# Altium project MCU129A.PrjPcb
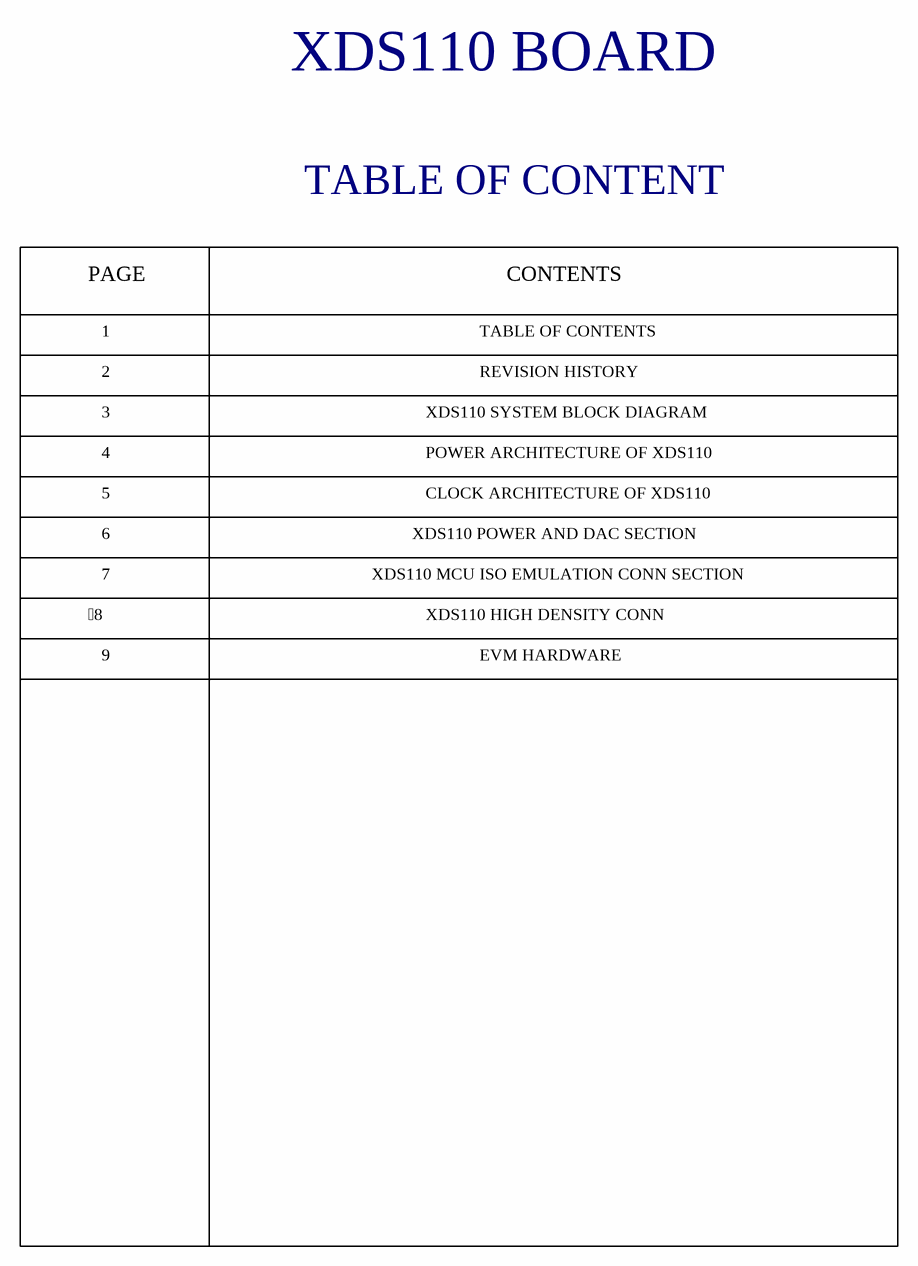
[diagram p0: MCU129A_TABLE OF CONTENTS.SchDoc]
DrawnBy: Texas Instruments; EVM_orderable: XDS110ISO-EVM; PCB_REV: A; PRJ_Customer: Public Release; PRJ_Engineer: Gus Martinez; PRJ_Number: MCU129; PRJ_Title: C2000 XDS110 Plug -In Board; SCH_REV: A; TID: N/A
9 sheets, 170 parts. Net scope: global (net labels, ports and power ports of the same name join across sheets).
Board file: MCU129A.PcbDoc
Sheets:
  MCU129A_TABLE OF CONTENTS.SchDoc
  MCU129A_REVISION_HISTORY.SchDoc
  MCU129A_SYSTEM_BLOCK_DIAG.SchDoc
  MCU129A_POWER_ARCHITECT.SchDoc
  MCU129A_CLOCK_ARCHITECTURE.SchDoc
  MCU129A_POWER_DAC_SECTION.SchDoc
  MCU129A_MCU_ISO_EMULATION_CONN.SchDoc
  MCU129A_HIGH_DENSITY_CONN.SchDoc
  MCU129A_EVM_Hardware.SchDoc

## Sheet MCU129A_TABLE OF CONTENTS.SchDoc
size 431 x 279 mm; Date: Not shown in title block; ApprovedBy: Not shown in title block; CheckedBy: Not shown in title block; Author: Not shown in title block; CompanyName: Not shown in title block; Engineer: Not shown in title block; Organization: Not shown in title block; Address1: Not shown in title block; Address2: Not shown in title block; Address3: Not shown in title block; Address4: Not shown in title block; DocumentNumber: 1; Revision: Use project parameter SCH_Rev; SheetNumber: 1; SheetTotal: 9; PageSetup: Record=PageOptions¦CenterHorizontal=True¦CenterVertical=True¦PrintScale=1.00¦XCorrection=1.00¦YCorrection=1.00¦PrintKind=0¦BorderSize=5000000¦LeftOffset=0¦BottomOffset=0¦Orientation=2¦PaperLength=1000¦PaperWidth=1000¦Scale=100¦PaperSource=15¦PrintQuality=600¦MediaType=1¦DitherType=10¦PaperKind=Letter¦PrintScaleMode=1

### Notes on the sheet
- XDS110 BOARD
- TABLE OF CONTENT
- PAGE
- 1
- TABLE OF CONTENTS
- CONTENTS
- 2
- REVISION HISTORY
- 3
- 4
- XDS110 SYSTEM BLOCK DIAGRAM
- POWER ARCHITECTURE OF XDS110
- 5
- 6
- XDS110 POWER AND DAC SECTION
- CLOCK ARCHITECTURE OF XDS110
- 7
- XDS110 MCU ISO EMULATION CONN SECTION
- 8
- 9
- XDS110 HIGH DENSITY CONN
- EVM HARDWARE

## Sheet MCU129A_REVISION_HISTORY.SchDoc
size 431 x 279 mm; Date: Not shown in title block; ApprovedBy: Not shown in title block; CheckedBy: Not shown in title block; Author: Not shown in title block; CompanyName: Not shown in title block; Engineer: Not shown in title block; Organization: Not shown in title block; Address1: Not shown in title block; Address2: Not shown in title block; Address3: Not shown in title block; Address4: Not shown in title block; DocumentNumber: 2; Revision: Use project parameter SCH_Rev; SheetNumber: 2; SheetTotal: 9; PageSetup: Record=PageOptions¦CenterHorizontal=True¦CenterVertical=True¦PrintScale=1.00¦XCorrection=1.00¦YCorrection=1.00¦PrintKind=0¦BorderSize=5000000¦LeftOffset=0¦BottomOffset=0¦Orientation=2¦PaperLength=1000¦PaperWidth=1000¦Scale=100¦PaperSource=15¦PrintQuality=600¦MediaType=1¦DitherType=10¦PaperKind=Letter¦PrintScaleMode=1
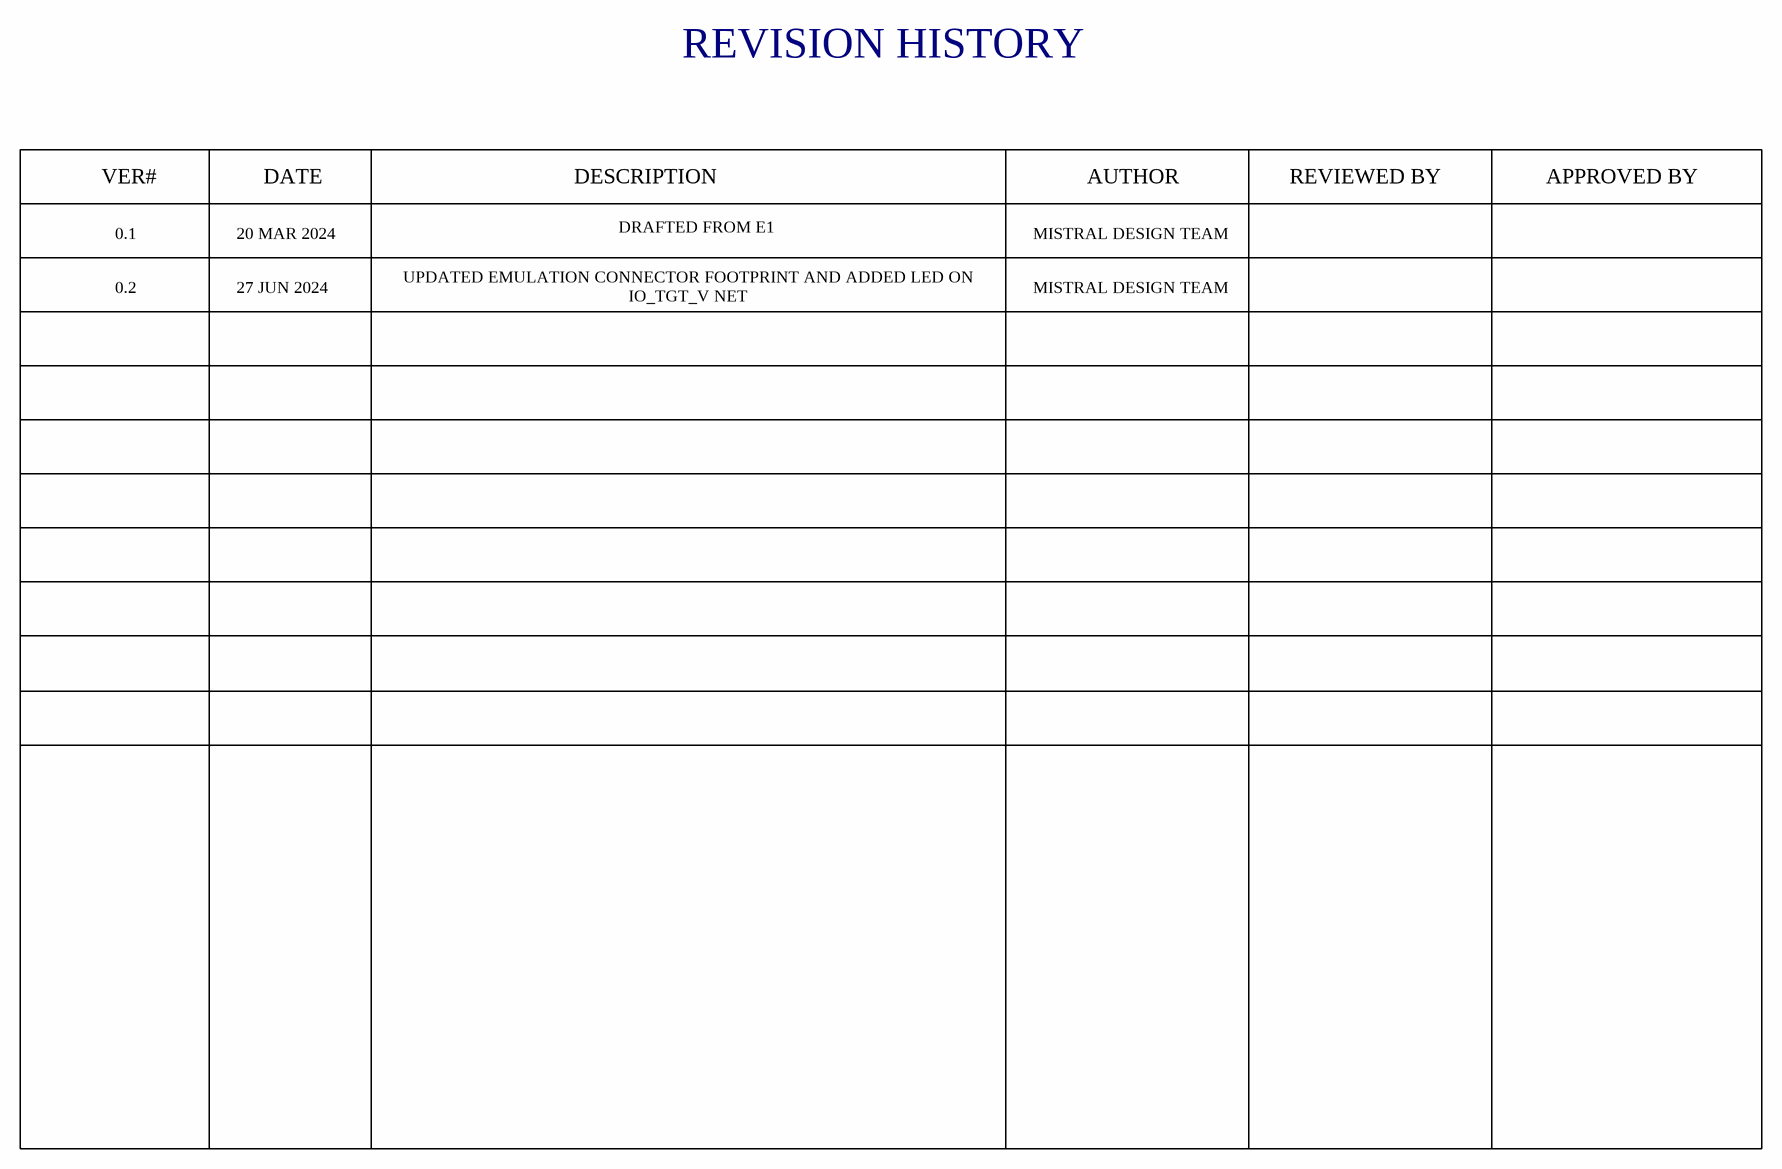
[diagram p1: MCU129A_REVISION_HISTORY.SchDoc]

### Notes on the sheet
- REVISION HISTORY
- VER#
- 0.1
- 20 MAR 2024
- DATE
- DESCRIPTION
- DRAFTED FROM E1
- MISTRAL DESIGN TEAM
- AUTHOR
- REVIEWED BY
- APPROVED BY
- 0.2
- 27 JUN 2024
- UPDATED EMULATION CONNECTOR FOOTPRINT AND ADDED LED ON IO_TGT_V NET

## Sheet MCU129A_SYSTEM_BLOCK_DIAG.SchDoc
size 431 x 279 mm; Date: Not shown in title block; ApprovedBy: Not shown in title block; CheckedBy: Not shown in title block; Author: Not shown in title block; CompanyName: Not shown in title block; Engineer: Not shown in title block; Organization: Not shown in title block; Address1: Not shown in title block; Address2: Not shown in title block; Address3: Not shown in title block; Address4: Not shown in title block; DocumentNumber: 3; Revision: Use project parameter SCH_Rev; SheetNumber: 3; SheetTotal: 9; PageSetup: Record=PageOptions¦CenterHorizontal=True¦CenterVertical=True¦PrintScale=1.00¦XCorrection=1.00¦YCorrection=1.00¦PrintKind=0¦BorderSize=5000000¦LeftOffset=0¦BottomOffset=0¦Orientation=2¦PaperLength=1000¦PaperWidth=1000¦Scale=100¦PaperSource=15¦PrintQuality=600¦MediaType=1¦DitherType=10¦PaperKind=Letter¦PrintScaleMode=1
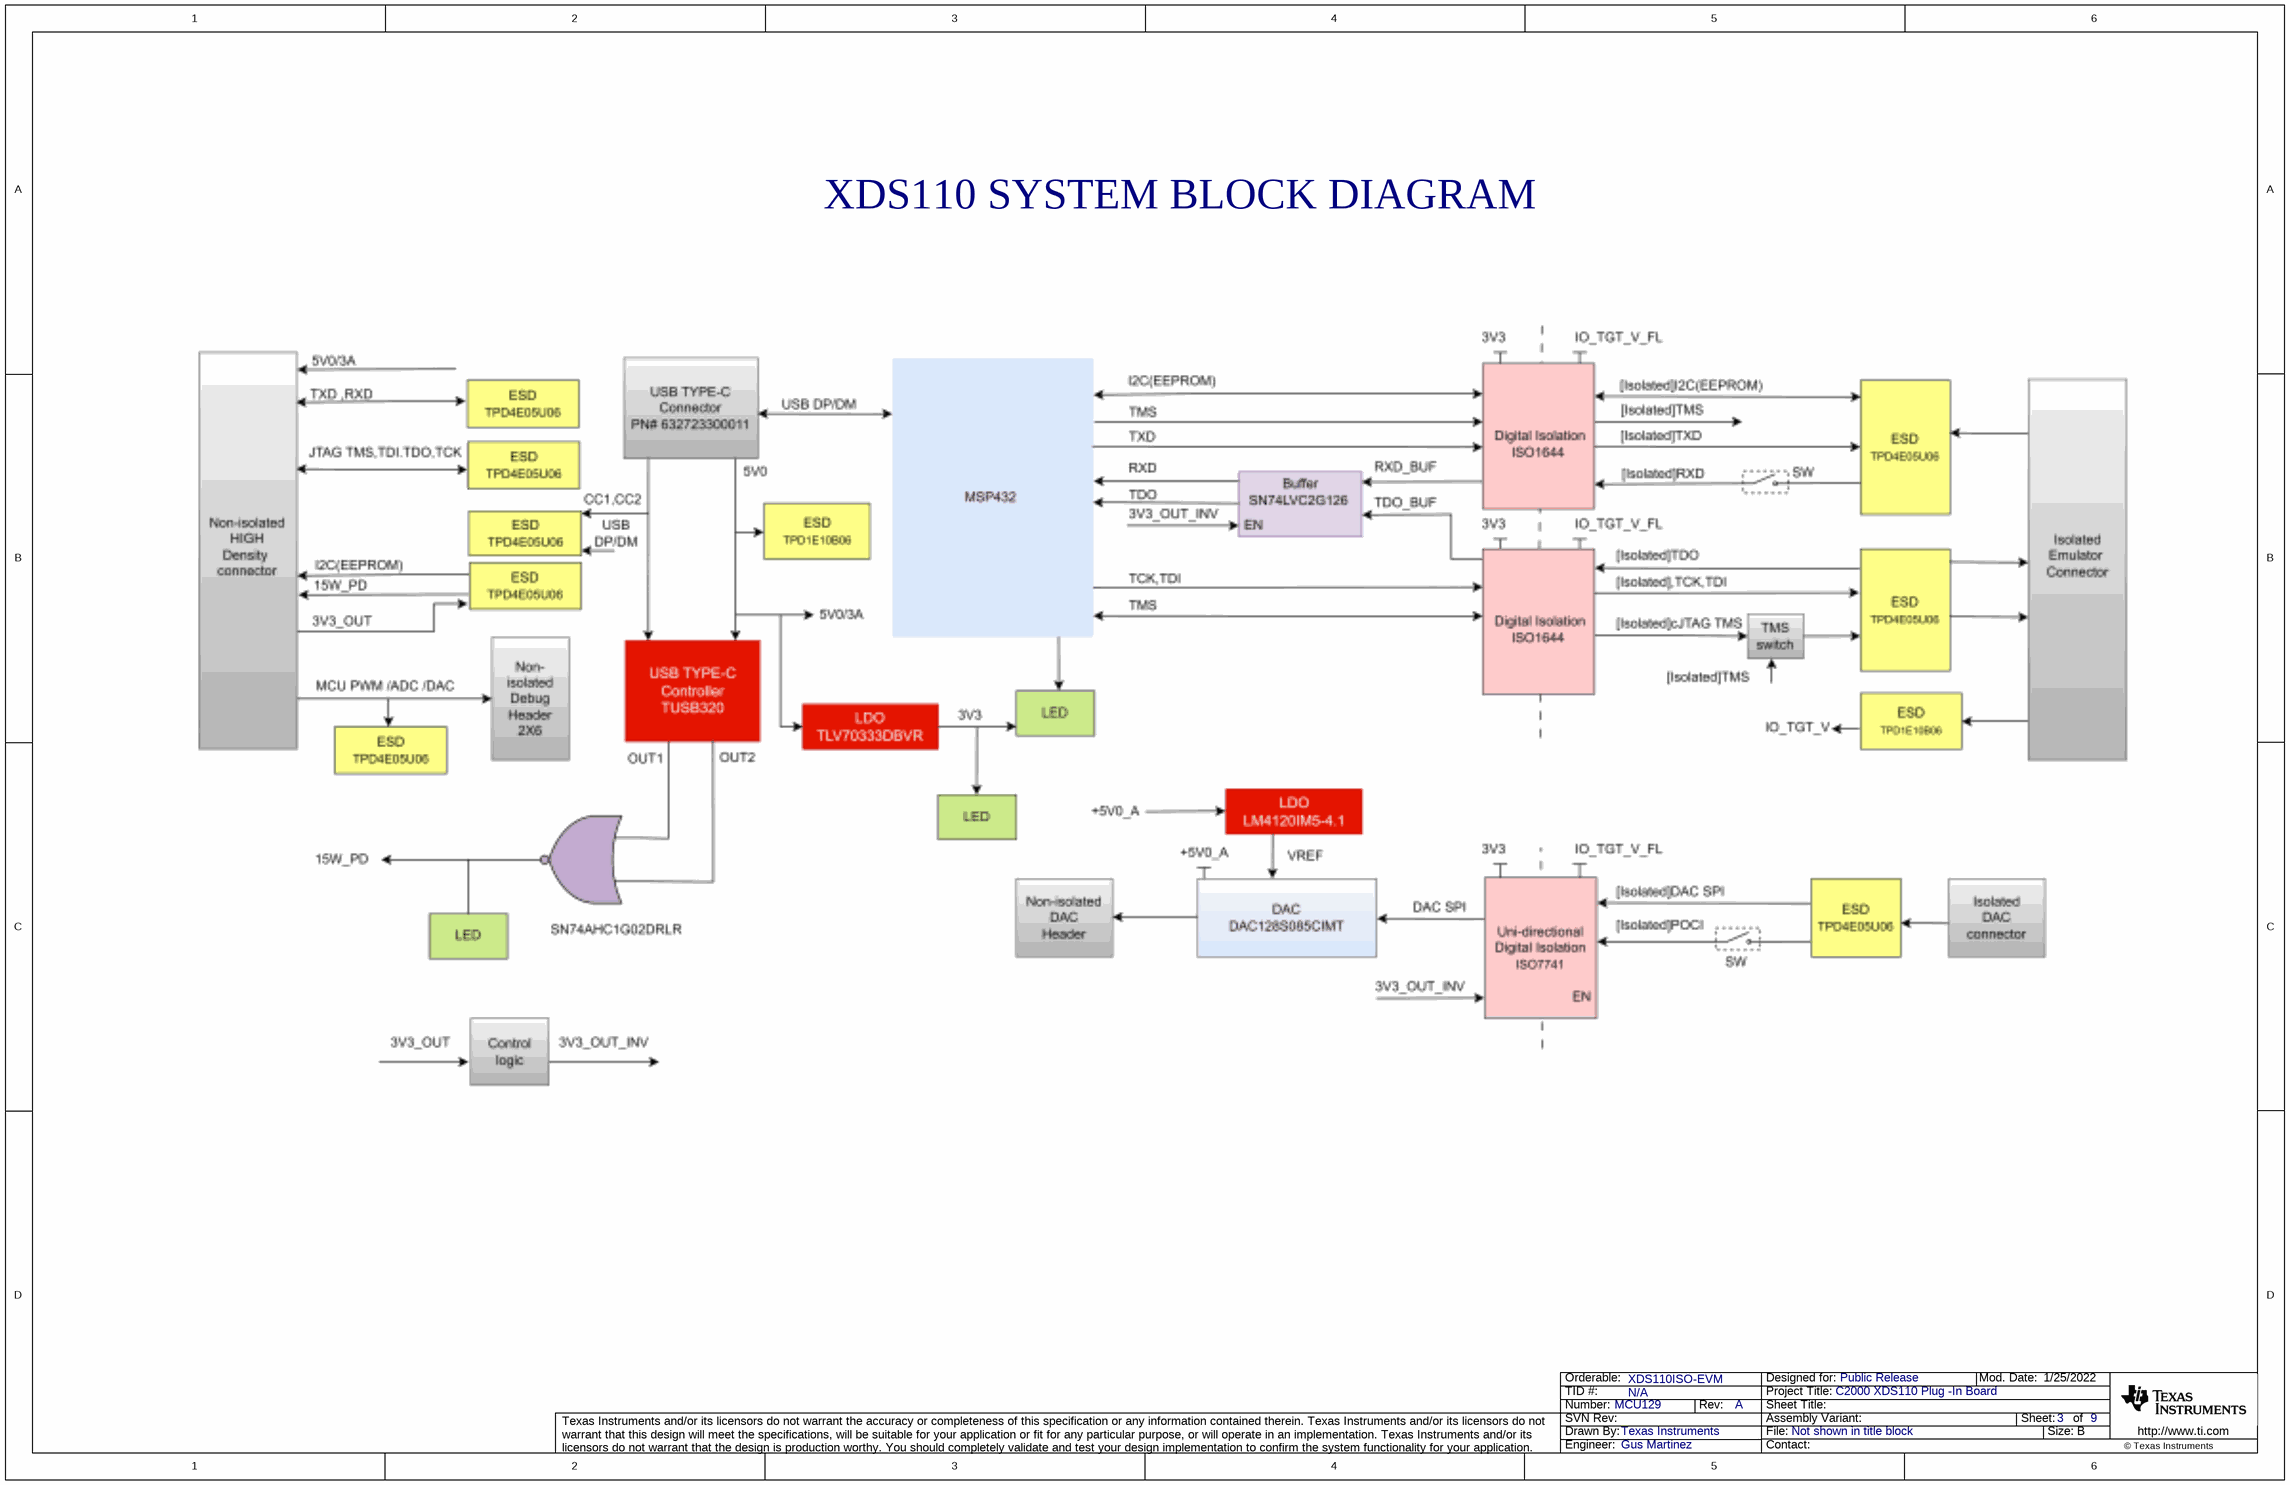
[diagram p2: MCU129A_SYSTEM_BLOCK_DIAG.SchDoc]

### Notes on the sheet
- XDS110 SYSTEM BLOCK DIAGRAM

## Sheet MCU129A_POWER_ARCHITECT.SchDoc
size 431 x 279 mm; Date: Not shown in title block; ApprovedBy: Not shown in title block; CheckedBy: Not shown in title block; Author: Not shown in title block; CompanyName: Not shown in title block; Engineer: Not shown in title block; Organization: Not shown in title block; Address1: Not shown in title block; Address2: Not shown in title block; Address3: Not shown in title block; Address4: Not shown in title block; DocumentNumber: 4; Revision: Use project parameter SCH_Rev; SheetNumber: 4; SheetTotal: 9; PageSetup: Record=PageOptions¦CenterHorizontal=True¦CenterVertical=True¦PrintScale=1.00¦XCorrection=1.00¦YCorrection=1.00¦PrintKind=0¦BorderSize=5000000¦LeftOffset=0¦BottomOffset=0¦Orientation=2¦PaperLength=1000¦PaperWidth=1000¦Scale=100¦PaperSource=15¦PrintQuality=600¦MediaType=1¦DitherType=10¦PaperKind=Letter¦PrintScaleMode=1
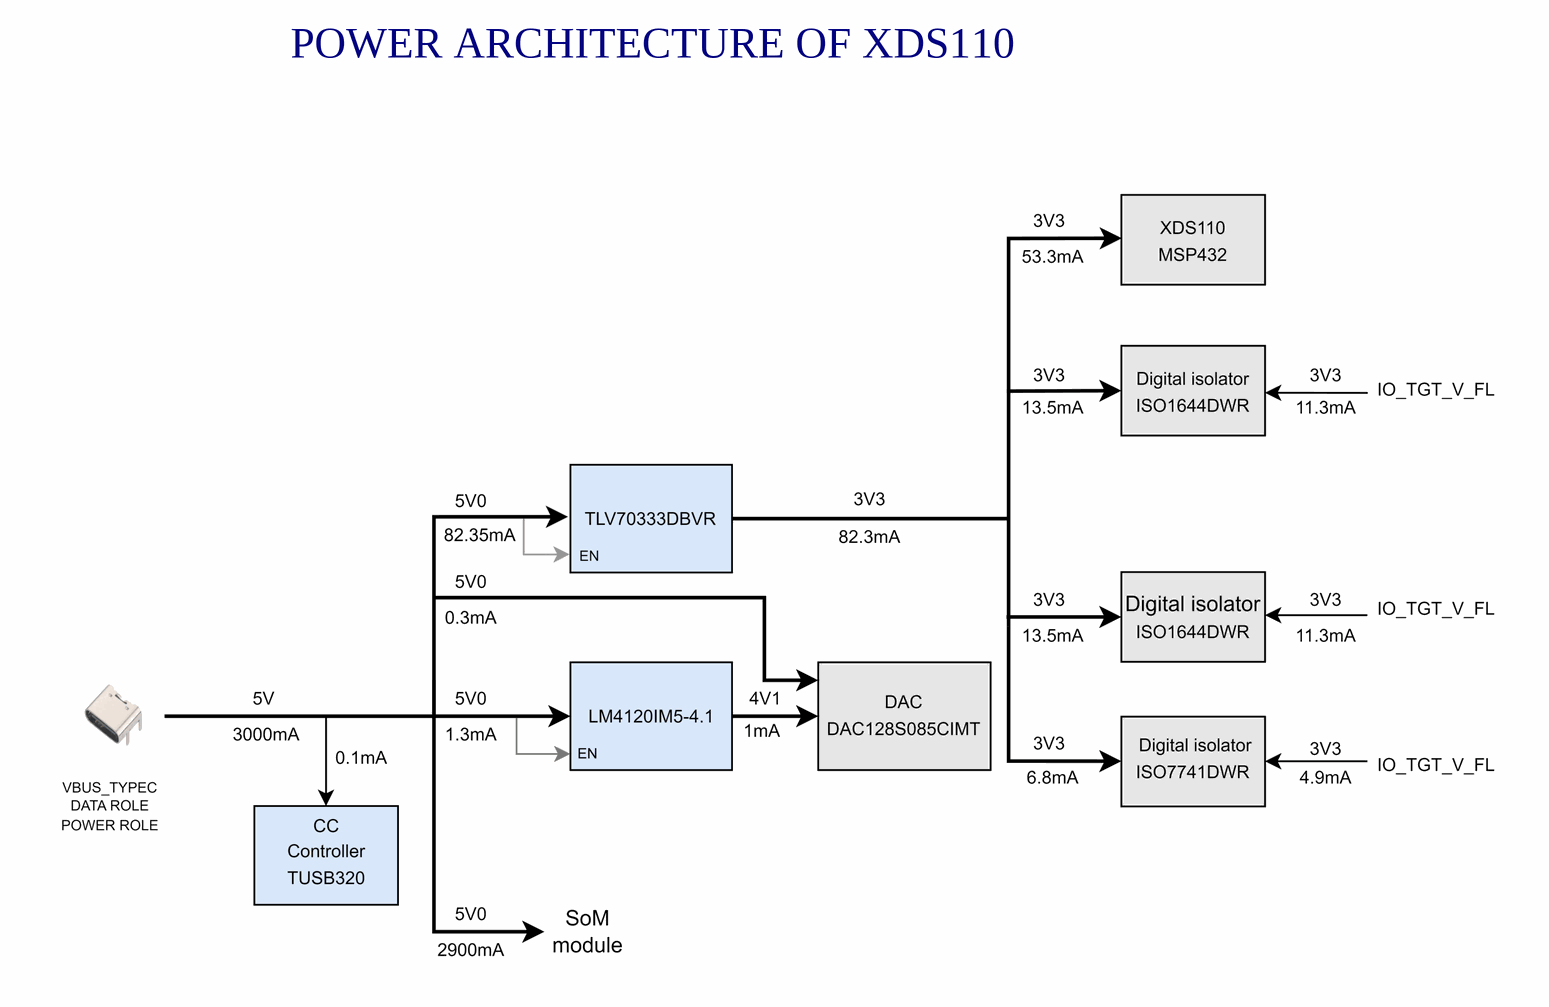
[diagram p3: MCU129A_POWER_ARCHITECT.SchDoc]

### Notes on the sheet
- POWER ARCHITECTURE OF XDS110

## Sheet MCU129A_CLOCK_ARCHITECTURE.SchDoc
size 431 x 279 mm; Date: Not shown in title block; ApprovedBy: Not shown in title block; CheckedBy: Not shown in title block; Author: Not shown in title block; CompanyName: Not shown in title block; Engineer: Not shown in title block; Organization: Not shown in title block; Address1: Not shown in title block; Address2: Not shown in title block; Address3: Not shown in title block; Address4: Not shown in title block; DocumentNumber: 5; Revision: Use project parameter SCH_Rev; SheetNumber: 5; SheetTotal: 9; PageSetup: Record=PageOptions¦CenterHorizontal=True¦CenterVertical=True¦PrintScale=1.00¦XCorrection=1.00¦YCorrection=1.00¦PrintKind=0¦BorderSize=5000000¦LeftOffset=0¦BottomOffset=0¦Orientation=2¦PaperLength=1000¦PaperWidth=1000¦Scale=100¦PaperSource=15¦PrintQuality=600¦MediaType=1¦DitherType=10¦PaperKind=Letter¦PrintScaleMode=1
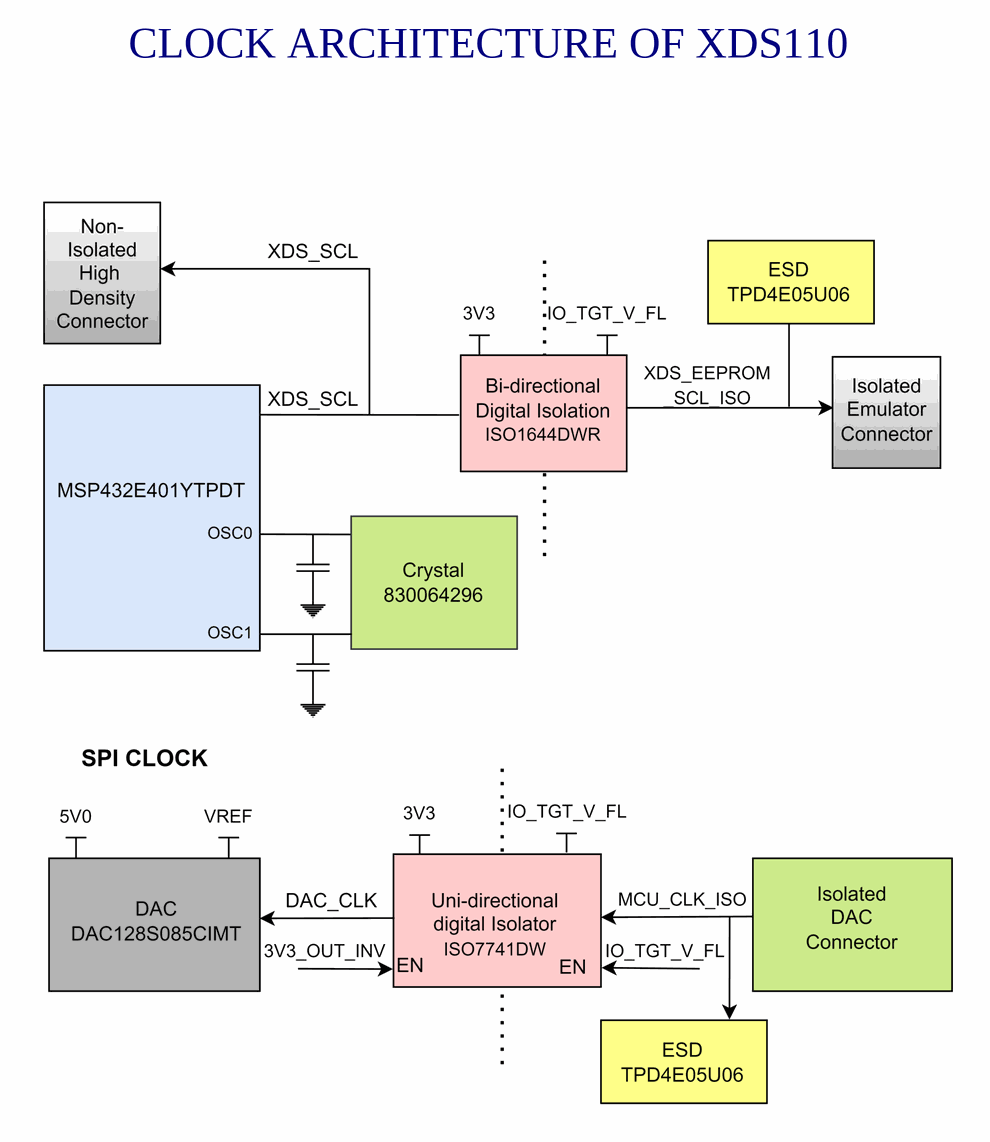
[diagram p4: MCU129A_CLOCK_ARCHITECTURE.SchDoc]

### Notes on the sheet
- CLOCK ARCHITECTURE OF XDS110

## Sheet MCU129A_POWER_DAC_SECTION.SchDoc
size 431 x 279 mm; DocumentNumber: 6; SheetNumber: 6; SheetTotal: 9
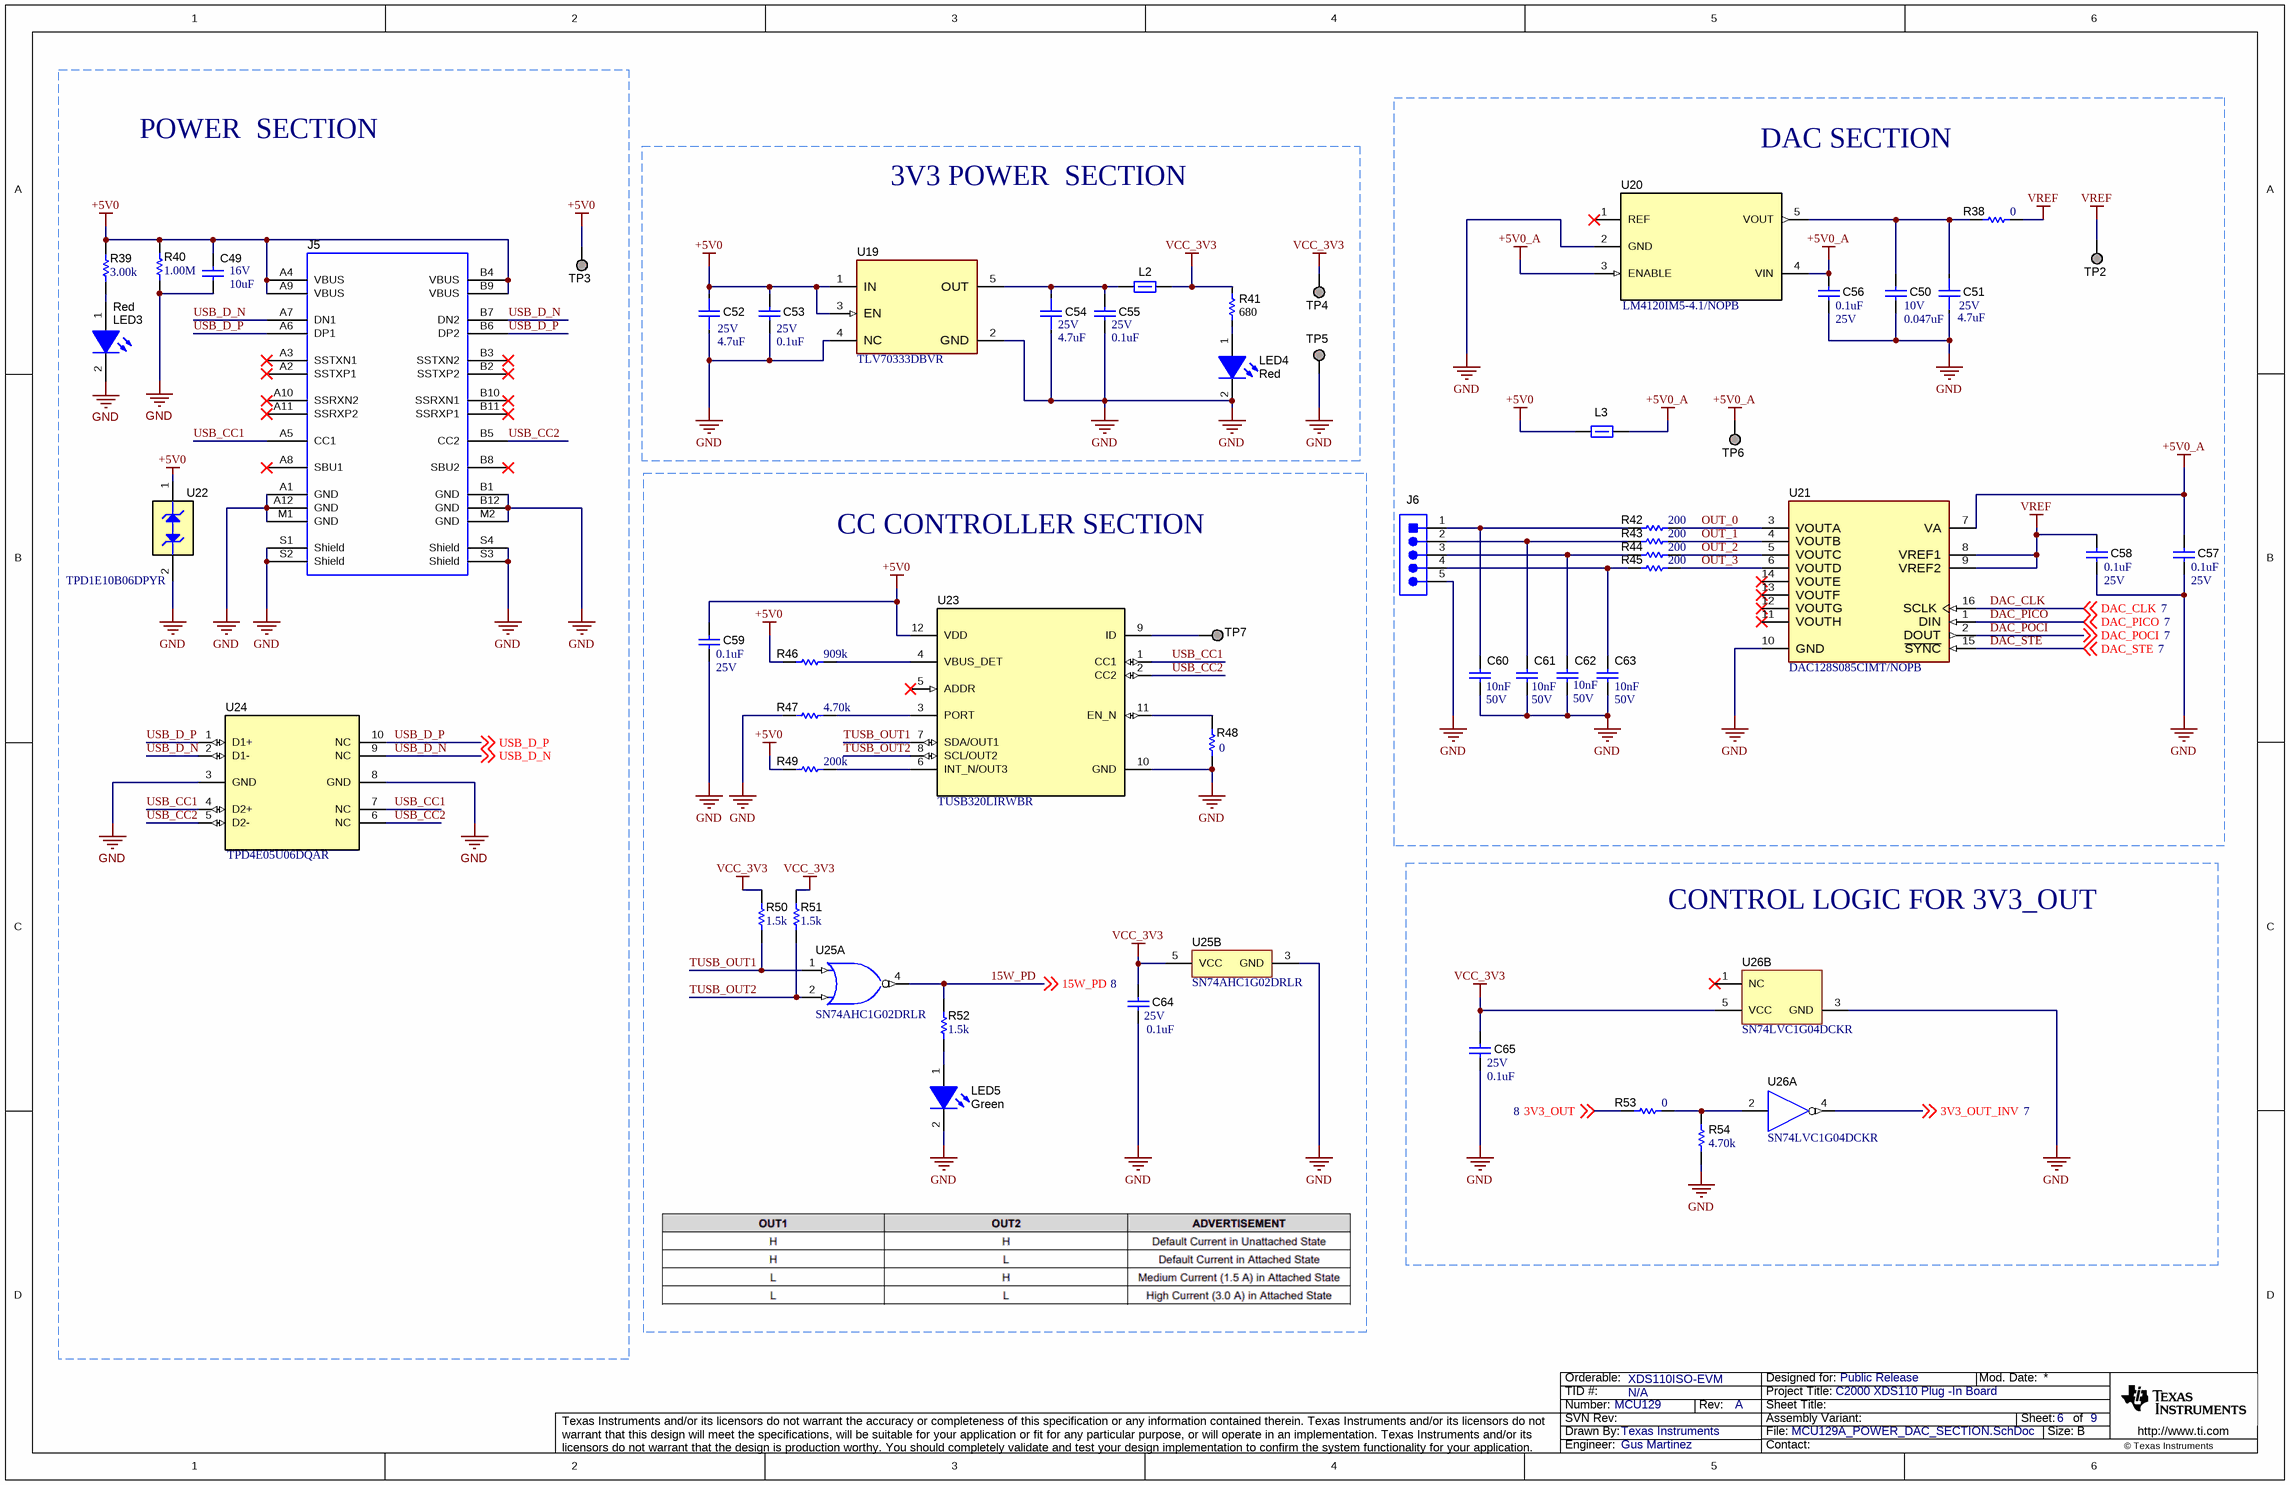
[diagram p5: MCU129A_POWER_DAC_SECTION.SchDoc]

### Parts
C49  VDC_V: 16V  ValueDisplayed: 10uF  [0603]  (hidden comment: GRM188R61C106MAALD)
C50  VDC_V: 10V  ValueDisplayed: 0.047uF  [0402]  (hidden comment: GRM155R71A473KA01D)
C51  VDC_V: 25V  ValueDisplayed: 4.7uF  [FP-GRM155C61E475ME15D_0402-MFG]  (hidden comment: GRM155C61E475ME15D)
C52  VDC_V: 25V  ValueDisplayed: 4.7uF  [FP-GRM155C61E475ME15D_0402-MFG]  (hidden comment: GRM155C61E475ME15D)
C53  ValueDisplayed: 0.1uF  Value2: 25V  [0402]  (hidden comment: GRM155R71E104KE14D)
C54  VDC_V: 25V  ValueDisplayed: 4.7uF  [FP-GRM155C61E475ME15D_0402-MFG]  (hidden comment: GRM155C61E475ME15D)
C55  ValueDisplayed: 0.1uF  Value2: 25V  [0402]  (hidden comment: GRM155R71E104KE14D)
C56  ValueDisplayed: 0.1uF  VDC_V: 25V  [0402]  (hidden comment: GRM155R71E104KE14D)
C57  ValueDisplayed: 0.1uF  VDC_V: 25V  [0402]  (hidden comment: GRM155R71E104KE14D)
C58  ValueDisplayed: 0.1uF  VDC_V: 25V  [0402]  (hidden comment: GRM155R71E104KE14D)
C59  ValueDisplayed: 0.1uF  Value2: 25V  [0402]  (hidden comment: GRM155R71E104KE14D)
C60  Cap_F: 10nF  VDC_V: 50V  [0603]  (hidden comment: GRM1885C1H103JA01D)
C61  Cap_F: 10nF  VDC_V: 50V  [0603]  (hidden comment: GRM1885C1H103JA01D)
C62  Cap_F: 10nF  VDC_V: 50V  [0603]  (hidden comment: GRM1885C1H103JA01D)
C63  Cap_F: 10nF  VDC_V: 50V  [0603]  (hidden comment: GRM1885C1H103JA01D)
C64  ValueDisplayed: 0.1uF  Value2: 25V  [0402]  (hidden comment: GRM155R71E104KE14D)
C65  ValueDisplayed: 0.1uF  Value2: 25V  [0402]  (hidden comment: GRM155R71E104KE14D)
J5  632723300011  [Wurth_632_723_300_011]  (value not drawn)
J6  TSW-105-08-G-S-RA  [TSW-105-08-G-S-RA]  (value not drawn)
L2  BLM15AG100SN1D  [0402]  (value not drawn)
L3  BLM15AG100SN1D  [0402]  (value not drawn)
LED3  value Red  [APHHS1005_Red]  (hidden comment: APHHS1005SURCK)
LED4  value Red  [APHHS1005_Red]  (hidden comment: APHHS1005SURCK)
LED5  value Green  [APHHS1005_Green]  (hidden comment: APHHS1005CGCK)
R38  ValueDisplayed: 0  [0402]  (hidden comment: CRCW04020000Z0ED)
R39  ValueDisplayed: 3.00k  [0402]  (hidden comment: RC0402FR-073KL)
R40  ValueDisplayed: 1.00M  [0402]  (hidden comment: ERJ-2RKF1004X)
R41  ValueDisplayed: 680  [0402]  (hidden comment: CRCW0402680RJNED)
R42  ValueDisplayed: 200  [0603]  (hidden comment: CRCW0603200RFKEA)
R43  ValueDisplayed: 200  [0603]  (hidden comment: CRCW0603200RFKEA)
R44  ValueDisplayed: 200  [0603]  (hidden comment: CRCW0603200RFKEA)
R45  ValueDisplayed: 200  [0603]  (hidden comment: CRCW0603200RFKEA)
R46  ValueDisplayed: 909k  [0402]  (hidden comment: CRCW0402909KFKED)
R47  ValueDisplayed: 4.70k  [0402]  (hidden comment: CRG0402F4K7)
R48  ValueDisplayed: 0  [0402]  (hidden comment: CRCW04020000Z0ED)
R49  ValueDisplayed: 200k  [0402]  (hidden comment: CRCW0402200KFKED)
R50  ValueDisplayed: 1.5k  [0402]  (hidden comment: CRCW04021K50JNED)
R51  ValueDisplayed: 1.5k  [0402]  (hidden comment: CRCW04021K50JNED)
R52  ValueDisplayed: 1.5k  [0402]  (hidden comment: CRCW04021K50JNED)
R53  ValueDisplayed: 0  [0402]  (hidden comment: CRCW04020000Z0ED)
R54  ValueDisplayed: 4.70k  [0402]  (hidden comment: CRG0402F4K7)
TP2  TP_SM_1MM  [TP_SM_1MM]  (value not drawn)  (no BOM)
TP3  CMP-0078143-4  [TESTPOINT]  (value not drawn)  (no BOM)
TP4  CMP-0078143-4  [TESTPOINT]  (value not drawn)  (no BOM)
TP5  CMP-0078143-4  [TESTPOINT]  (value not drawn)  (no BOM)
TP6  TP_SM_1MM  [TP_SM_1MM]  (value not drawn)  (no BOM)
TP7  TP_SM_1MM  [TP_SM_1MM]  (value not drawn)  (no BOM)
U19  TLV70333DBVR  [DBV0005A-MFG]
U20  LM4120IM5-4.1/NOPB  [DBV0005A_N]
U21  DAC128S085CIMT/NOPB  [PW0016A-MFG]
U22  TPD1E10B06DPYR  [DPY0002A]
U23  TUSB320LIRWBR  [RWB0012A]
U24  TPD4E05U06DQAR  [DQA0010A]
U25  SN74AHC1G02DRLR  [DRL0005A]  (parts A,B of 2)
U26  SN74LVC1G04DCKR  [DCK0005A_N]  (parts A,B of 2)

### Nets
+5V0: C49.1 C52.2 C53.2 C59.2 J5.A4(VBUS) J5.A9(VBUS) J5.B4(VBUS) J5.B9(VBUS) L3.1 R39.2 R40.2 R46.1 R49.1 TP3.1 U19.1(IN) U19.3(EN) U22.1(K) U23.12(VDD)
+5V0_A: C56.1 C57.2 L3.2 TP6.1 U20.3(ENABLE) U20.4(VIN) U21.7(VA)
GND: C49.2 C50.2 C51.1 C52.1 C53.1 C54.1 C55.1 C56.2 C57.1 C58.1 C59.1 C60.2 C61.2 C62.2 C63.2 C64.1 C65.1 J5.A1(GND) J5.A12(GND) J5.B1(GND) J5.B12(GND) J5.M1(GND) J5.M2(GND) J5.S1(Shield) J5.S2(Shield) J5.S3(Shield) J5.S4(Shield) J6.5 LED3.2(K) LED4.2(K) LED5.2(K) R40.1 R47.2 R48.1 R54.1 TP5.1 U19.2(GND) U19.4(NC) U20.2(GND) U21.10(GND) U22.2(A) U23.10(GND) U24.3(GND) U24.8(GND) U25.3(GND) U26.3(GND)
VCC_3V3: C64.2 C65.2 L2.2 R41.2 R50.2 R51.2 TP4.1 U25.5(VCC) U26.5(VCC)
VREF: C58.2 R38.1 TP2.1 U21.8(VREF1) U21.9(VREF2)
3V3_OUT: R53.2 ; off-sheet 3V3_OUT
3V3_OUT_INV: U26.4(Y) ; off-sheet 3V3_OUT_INV
15W_PD: R52.2 U25.4(Y) ; off-sheet 15W_PD
DAC_CLK: U21.16(SCLK) ; off-sheet DAC_CLK
DAC_PICO: U21.1(DIN) ; off-sheet DAC_PICO
DAC_POCI: U21.2(DOUT) ; off-sheet DAC_POCI
DAC_STE: U21.15(~{SYNC}) ; off-sheet DAC_STE
OUT_0: R42.2 U21.3(VOUTA)
OUT_1: R43.2 U21.4(VOUTB)
OUT_2: R44.2 U21.5(VOUTC)
OUT_3: R45.2 U21.6(VOUTD)
TUSB_OUT1: R50.1 U23.7(SDA/OUT1) U25.1(A)
TUSB_OUT2: R51.1 U23.8(SCL/OUT2) U25.2(B)
USB_CC1: J5.A5(CC1) U23.1(CC1) U24.4(D2+) U24.7(NC)
USB_CC2: J5.B5(CC2) U23.2(CC2) U24.5(D2-) U24.6(NC)
USB_D_N: J5.A7(DN1) J5.B7(DN2) U24.2(D1-) U24.9(NC) ; off-sheet USB_D_N
USB_D_P: J5.A6(DP1) J5.B6(DP2) U24.1(D1+) U24.10(NC) ; off-sheet USB_D_P
NetC50_1: C50.1 C51.2 R38.2 U20.5(VOUT)
NetC54_2: C54.2 C55.2 L2.1 U19.5(OUT)
NetC60_1: C60.1 J6.1 R42.1
NetC61_1: C61.1 J6.2 R43.1
NetC62_1: C62.1 J6.3 R44.1
NetC63_1: C63.1 J6.4 R45.1
NetLED3_1: LED3.1(A) R39.1
NetLED4_1: LED4.1(A) R41.1
NetLED5_1: LED5.1(A) R52.1
NetR46_2: R46.2 U23.4(VBUS_DET)
NetR47_1: R47.1 U23.3(PORT)
NetR48_2: R48.2 U23.11(EN_N)
NetR49_2: R49.2 U23.6(INT_N/OUT3)
NetR53_1: R53.1 R54.2 U26.2(A)
NetTP7_1: TP7.1 U23.9(ID)

Not connected (* = marked no-connect by the designer): J5 A2(SSTXP1)* A3(SSTXN1)* A8(SBU1)* A10(SSRXN2)* A11(SSRXP2)* B2(SSTXP2)* B3(SSTXN2)* B8(SBU2)* B10(SSRXN1)* B11(SSRXP1)*; U20 1(REF)*; U21 11(VOUTH)* 12(VOUTG)* 13(VOUTF)* 14(VOUTE)*; U23 5(ADDR)*; U26 1(NC)*

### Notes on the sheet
- POWER  SECTION
- DAC SECTION
- 3V3 POWER  SECTION
- Type @ to refer to a designator or a net
- CC CONTROLLER SECTION
- CONTROL LOGIC FOR 3V3_OUT

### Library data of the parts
C49 = CMP-0007336-5: CAP, CERM, 10 uF, 16 V, +/- 20%, X5R, 0603; Manufacturer: MuRata; TaMin_C: -55°C; Polarized: N; SizeAreaWB_mm2: 4.68; Value1: Unknown; U/M: EA; Value: 10uF; TaMax_C: 85°C; SizeZ_mm: 1; SizeX_mm: 1.6; SizeY_mm: 0.8; SizeArea_mm2: 1.28; Cap_F: 10µF; AEC Category: Q200
C50 = CMP-0006634-2: CAP, CERM, 0.047 uF, 10 V, +/- 10%, X7R, 0402; Manufacturer: MuRata; TaMin_C: -55°C; Polarized: N; SizeAreaWB_mm2: 3; Value1: Unknown; U/M: EA; TaMax_C: 125°C; SizeZ_mm: 0.6; SizeX_mm: 1; SizeY_mm: 0.5; Cap_F: 47nF; AEC Category: Q200
C51 C52 C54 = CMP-0120206-1: 4.7 µF ±20% 25V Ceramic Capacitor X5S 0402 (1005 Metric); Manufacturer: Murata; TempCo: 22%; Value: 4.7µF; SizeZ_mm: 0.7mm; AEC Qualified: No
C53 C55-C59 C64 C65 = CMP-0006659-2: CAP, CERM, 0.1 uF, 25 V, +/- 10%, X7R, 0402; Manufacturer: MuRata; Polarized: N; Value: 0.1uF; U/M: EA; Cap_F: 100nF; Value1: Unknown; TaMin_C: -55°C; TaMax_C: 125°C; SizeArea_mm2: 0.5; SizeAreaWB_mm2: 3; SizeX_mm: 1; SizeZ_mm: 0.6; AEC Category: Q200
C60-C63 = CMP-0007174-4: CAP, CERM, 0.01 uF, 50 V, +/- 5%, C0G/NP0, 0603; Manufacturer: MuRata; TaMin_C: -55°C; Polarized: N; SizeAreaWB_mm2: 4.68; Value1: Unknown; U/M: EA; Value: 0.01uF; TaMax_C: 125°C; SizeZ_mm: 1; SizeX_mm: 1.6; SizeY_mm: 0.8; SizeArea_mm2: 1.28; AEC Category: Q200
J5 = CMP-0080891-1: Connector, Receptacle, USB Type C, R/A; Manufacturer: Wurth Elektronik; Current_A: 3A; Gender: Female; Voltage_V: 5V; ContactFinish: Gold; Cert_UL: Y
J6 = CMP-0055979-1: Header, 100mil, 5x1, Gold, R/A, TH; Manufacturer: Samtec; Cert_VDE: N; CNHeader: FALSE; Current_A: 6.3A; Gender: Male; Cert_CSA: Y; Voltage_V: 550V; Row_Count: 1; Pitch_mm: 2.54
L2 L3 = CMP-0003309-1: Ferrite Bead, 10 ohm @ 100 MHz, 1 A, 0402; Manufacturer: MuRata; ZTyp@100MHz_Ohm: 10; SizeAreaWB_mm2: 3; DCR_ohm: 25m; Value1: 0.025 ohm; Value: 10 ohm; Imax_A: 1A; SizeZ_mm: 0.6; SizeX_mm: 1; SizeY_mm: 0.5
LED3 LED4 = CMP-0067681-2: LED, Red, SMD; Manufacturer: Kingbright; Vf_V: 1.95V; SizeAreaWB_mm2: 3.0; Tjmax_C: 85°C; SizeX_mm: 1.0; Io_A: 20mA; SizeArea_mm2: 0.5; Vr_V: 5V; Value1: 0.075W; SizeZ_mm: 0.6; Angle: 120.0; Ir_A: 10µA; Power_TotalModule: 75mW
LED5 = CMP-0067682-2: LED, Green, SMD; Manufacturer: Kingbright; Value1: 0.075W; Vf_V: 2.1V; Vr_V: 5V; SizeArea_mm2: 0.5; Power_TotalModule: 75mW; Tjmax_C: 85°C; Angle: 120.0; SizeAreaWB_mm2: 3.0; SizeX_mm: 1.0; Ir_A: 10µA; Io_A: 20mA; SizeZ_mm: 0.6
R38 R48 R53 = CMP-0026822-3: RES, 0, 5%, 0.063 W, AEC-Q200 Grade 0, 0402; Manufacturer: Vishay-Dale; Power_W: 63mW; TempCo: 200 ppm/C; Value_Code: 0000; Value: 0; EIA_Code: E24; SizeX_mm: 1; SizeY_mm: 0.5; SizeZ_mm: 0.6; Value2: 0.063W; AEC Qualified: Y; VDC_V: 50V; AEC Category: Q200
R39 = CMP-0026733-1: RES, 3.00 k, 1%, 0.0625 W, 0402; Manufacturer: Yageo America; Power_W: 62.5mW; TempCo: 100 ppm/C; Value_Code: 3k00; U/M: EA; Value: 3.00k; Res_ohm: 3k; SizeX_mm: 1; SizeY_mm: 0.5; SizeZ_mm: 0.6; AEC Qualified: N; VDC_V: 50V; AEC Category: Q200
R40 = CMP-0026660-1: RES, 1.00 M, 1%, 0.1 W, 0402; Manufacturer: Panasonic; Power_W: 100mW; TempCo: 100 ppm/C; Value_Code: 1M00; U/M: EA; Value: 1.00Meg; EIA_Code: E96; Res_ohm: 1M; SizeX_mm: 1; SizeY_mm: 0.5; SizeZ_mm: 0.6; Value2: 0.1W; VDC_V: 50V; AEC Category: Q200
R41 = CMP-0026962-3: RES, 680, 5%, 0.063 W, AEC-Q200 Grade 0, 0402; Manufacturer: Vishay-Dale; Power_W: 63mW; TempCo: 200 ppm/C; Value_Code: 680R; Value: 680; EIA_Code: E24; SizeX_mm: 1; SizeY_mm: 0.5; SizeZ_mm: 0.6; Value2: 0.063W; AEC Qualified: Y; VDC_V: 50V; AEC Category: Q200; AEC Grade: 0
R42-R45 = CMP-0022201-5: RES, 200, 1%, 0.1 W, AEC-Q200 Grade 0, 0603; Manufacturer: Vishay-Dale; Power_W: 100mW; TempCo: 100 ppm/C; Value_Code: 200R; Value: 200; EIA_Code: E96; SizeX_mm: 1.6; SizeY_mm: 0.8; SizeZ_mm: 1; Value2: 0.1W; SizeArea_mm2: 1.28; AEC Qualified: Y; VDC_V: 75V; AEC Category: Q200; AEC Grade: 0
R46 = CMP-0026603-2: RES, 909 k, 1%, 0.063 W, AEC-Q200 Grade 0, 0402; Manufacturer: Vishay-Dale; Power_W: 63mW; TempCo: 100 ppm/C; Value: 909k; EIA_Code: E96; SizeX_mm: 1; SizeY_mm: 0.5; SizeZ_mm: 0.6; Value2: 0.063W; AEC Qualified: Y; VDC_V: 50V; AEC Category: Q200; AEC Grade: 0
R47 R54 = CMP-0026631-1: RES, 4.70 k, 1%, 0.063 W, 0402; Manufacturer: TE Connectivity; Power_W: 63mW; TempCo: 100 ppm/C; Value_Code: 4k70; U/M: EA; Value: 4.70k; Res_ohm: 4.7k; SizeX_mm: 1; SizeY_mm: 0.5; SizeZ_mm: 0.6; Value2: 0.063W; AEC Qualified: N; AEC Category: Q200
R49 = CMP-0026158-2: RES, 200 k, 1%, 0.063 W, AEC-Q200 Grade 0, 0402; Manufacturer: Vishay-Dale; Power_W: 63mW; TempCo: 100 ppm/C; Value: 200k; EIA_Code: E96; SizeX_mm: 1; SizeY_mm: 0.5; SizeZ_mm: 0.6; Value2: 0.063W; AEC Qualified: Y; VDC_V: 50V; AEC Category: Q200; AEC Grade: 0
R50-R52 = CMP-0026856-5: RES, 1.5 k, 5%, 0.063 W, AEC-Q200 Grade 0, 0402; Manufacturer: Vishay-Dale; Power_W: 63mW; TempCo: 200 ppm/C; Value_Code: 1k50; Value: 1.5k; EIA_Code: E24; SizeX_mm: 1; SizeY_mm: 0.5; SizeZ_mm: 0.6; Value2: 0.063W; AEC Qualified: Y; VDC_V: 50V; AEC Category: Q200; AEC Grade: 0
TP2 TP6 TP7 = CMP-0003825-1: 1mm Test Point, SMT; Manufacturer: Any
TP3-TP5 = CMP-0078143-4: TEST POINT.  No entry in BOM.
U19 = CMP-0091939-1: Linear Voltage Regulator IC Positive Fixed 1 Output 300mA SOT-23-5; Manufacturer: Texas Instruments; SizeZ_mm: 1.45mm; Nominal Supply Current: 35-370uA; TJmax_C: +125°C; Output Voltage: 3.3V; Dropout Voltage: 260mV; Standoff Height: 0mm; Accuracy Percentage: 2%; AEC Qualified: No; Max Supply Voltage: 5.5V; Number Of Outputs: 1; Min Supply Voltage: 2V
U20 = CMP-0079364-1: 0.2% 50ppm/°C Drift Precision Series Voltage Reference with Shutdown Enable, DBV0005A (SOT-23-5); Alternate PartNumber: LM4120IM5X-4.1/NOPB; Alternate Manufacturer: Texas Instruments; Green_Lifecycle: Active; SizeAreaWB_mm2: 14.82; Green_REACh: Passed; SizeZ_mm: 1.45; SizeX_mm: 2.8; SizeY_mm: 2.9; SizeArea_mm2: 8.12; CompType: IC; AEC Qualified: N; AEC Category: Q200
U21 = CMP-0097843-1: DAC 8-CH Resistor-String 12-bit 16-Pin TSSOP Rail; Manufacturer: Texas Instruments; Max Supply Voltage: 5.5V; Number Of Channels: 8; TaMax_C: +125°C; SizeZ_mm: 1.2mm; TaMin_C: -40°C; TJmax_C: +150°C; Nominal Supply Current: 460-650uA; AEC Qualified: No; Data Polarity: Single Ended; Resolution: 12bits; Min Supply Voltage: 2.7V; Standoff Height: 0.05mm; Interface: SPI,Other
U22 = CMP-0043093-4: Single-Channel ESD in 0402 Package With 10pF Capacitance and 6V Breakdown, DPY0002A (X1SON-2); Alternate PartNumber: TPD1E10B06DPYT; Manufacturer: Texas Instruments; IO Leakage Current(nA): 10; CompType: IC; SizeAreaWB_mm2: 3.2; SizeX_mm: 1.0; SizeY_mm: 0.6; Green_REACh: Passed; AEC Category: Q200; SizeZ_mm: 0.45; IEC 61000-4-2 Air-Gap(+/- kV): 30; Breakdown Voltage(Min)(V): 6; Rating: Catalog; Green_Lifecycle: Active; Eco-Plan: TBD; AEC Qualified: N
U23 = CMP-0073635-2: USB Type-C Configuration Channel Logic and Port Control, RWB0012A (X2QFN-12); Alternate Manufacturer: Texas Instruments; SizeAreaWB_mm2: 6.76; SizeZ_mm: 0.4; SizeX_mm: 1.6; SizeArea_mm2: 2.56; CompType: IC; AEC Category: Q200; AEC Qualified: N; Rating: Catalog
U24 = CMP-0073613-3: 4-Channel Ultra-Low-Capacitance IEC ESD Protection Diode, DQA0010A (USON-10); Alternate Manufacturer: Texas Instruments; Green_Lifecycle: Active; SizeAreaWB_mm2: 7.0; Green_REACh: Passed; SizeZ_mm: 0.55; SizeX_mm: 1.0; SizeY_mm: 2.5; CompType: IC; AEC Category: Q200; AEC Qualified: N
U25 = CMP-0051530-2: Single 2-Input Positive-NOR Gate, DRL0005A, LARGE T&R; Manufacturer: Texas Instruments; Schmitt Trigger: No; Technology Family: AHC; Logic: True; Gate Type: NOR; Output Type: CMOS; Sub-Family: NAND Gate; Rating: Catalog; F @ Nom Voltage(Max)(Mhz): 75; ICC @ Nom Voltage(Max)(mA): 0.01; tpd @ Nom Voltage(Max)(ns): 11.4,7.5; Voltage(Nom)(V): 3.3,5; Output Drive (IOL/IOH)(Max)(mA): 50/-50; VCC(Max)(V): 5.5; VCC(Min)(V): 2; Bits(#): 1; AEC Category: Q200; AEC Qualified: N; CompType: IC; SizeArea_mm2: 2.56; SizeX_mm: 1.6; SizeZ_mm: 0.6
U26 = CMP-0051684-3: Single Inverter, DCK0005A, LARGE T&R; Manufacturer: Texas Instruments; Input Type: CMOS/TTL; Output Drive (IOL/IOH)(Max)(mA): 32/-32; Sub-Family: Inverting Buffer/Driver; VCC(Min)(V): 1.65; Bits(#): 1; Schmitt Trigger: No; Technology Family: LVC; Rating: Catalog; ICC @ Nom Voltage(Max)(mA): 0.01; tpd @ Nom Voltage(Max)(ns): 7.5,5.2,4.2,3.7; Voltage(Nom)(V): 1.8,2.5,3.3,5; F @ Nom Voltage(Max)(Mhz): 150; Output Type: CMOS; VCC(Max)(V): 5.5; Logic: Inverting; AEC Category: Q200; AEC Qualified: N; CompType: IC; SizeAreaWB_mm2: 9.3; SizeArea_mm2: 4.2; SizeX_mm: 2.1; SizeY_mm: 2.0; SizeZ_mm: 1.1

## Sheet MCU129A_MCU_ISO_EMULATION_CONN.SchDoc
size 431 x 279 mm; Date: Not shown in title block; ApprovedBy: Not shown in title block; CheckedBy: Not shown in title block; Author: Not shown in title block; CompanyName: Not shown in title block; Engineer: Not shown in title block; Organization: Not shown in title block; Address1: Not shown in title block; Address2: Not shown in title block; Address3: Not shown in title block; Address4: Not shown in title block; DocumentNumber: 7; Revision: Use project parameter SCH_Rev; SheetNumber: 7; SheetTotal: 9; PageSetup: Record=PageOptions¦CenterHorizontal=True¦CenterVertical=True¦PrintScale=1.00¦XCorrection=1.00¦YCorrection=1.00¦PrintKind=0¦BorderSize=5000000¦LeftOffset=0¦BottomOffset=0¦Orientation=2¦PaperLength=1000¦PaperWidth=1000¦Scale=100¦PaperSource=15¦PrintQuality=600¦MediaType=1¦DitherType=10¦PaperKind=Letter¦PrintScaleMode=1
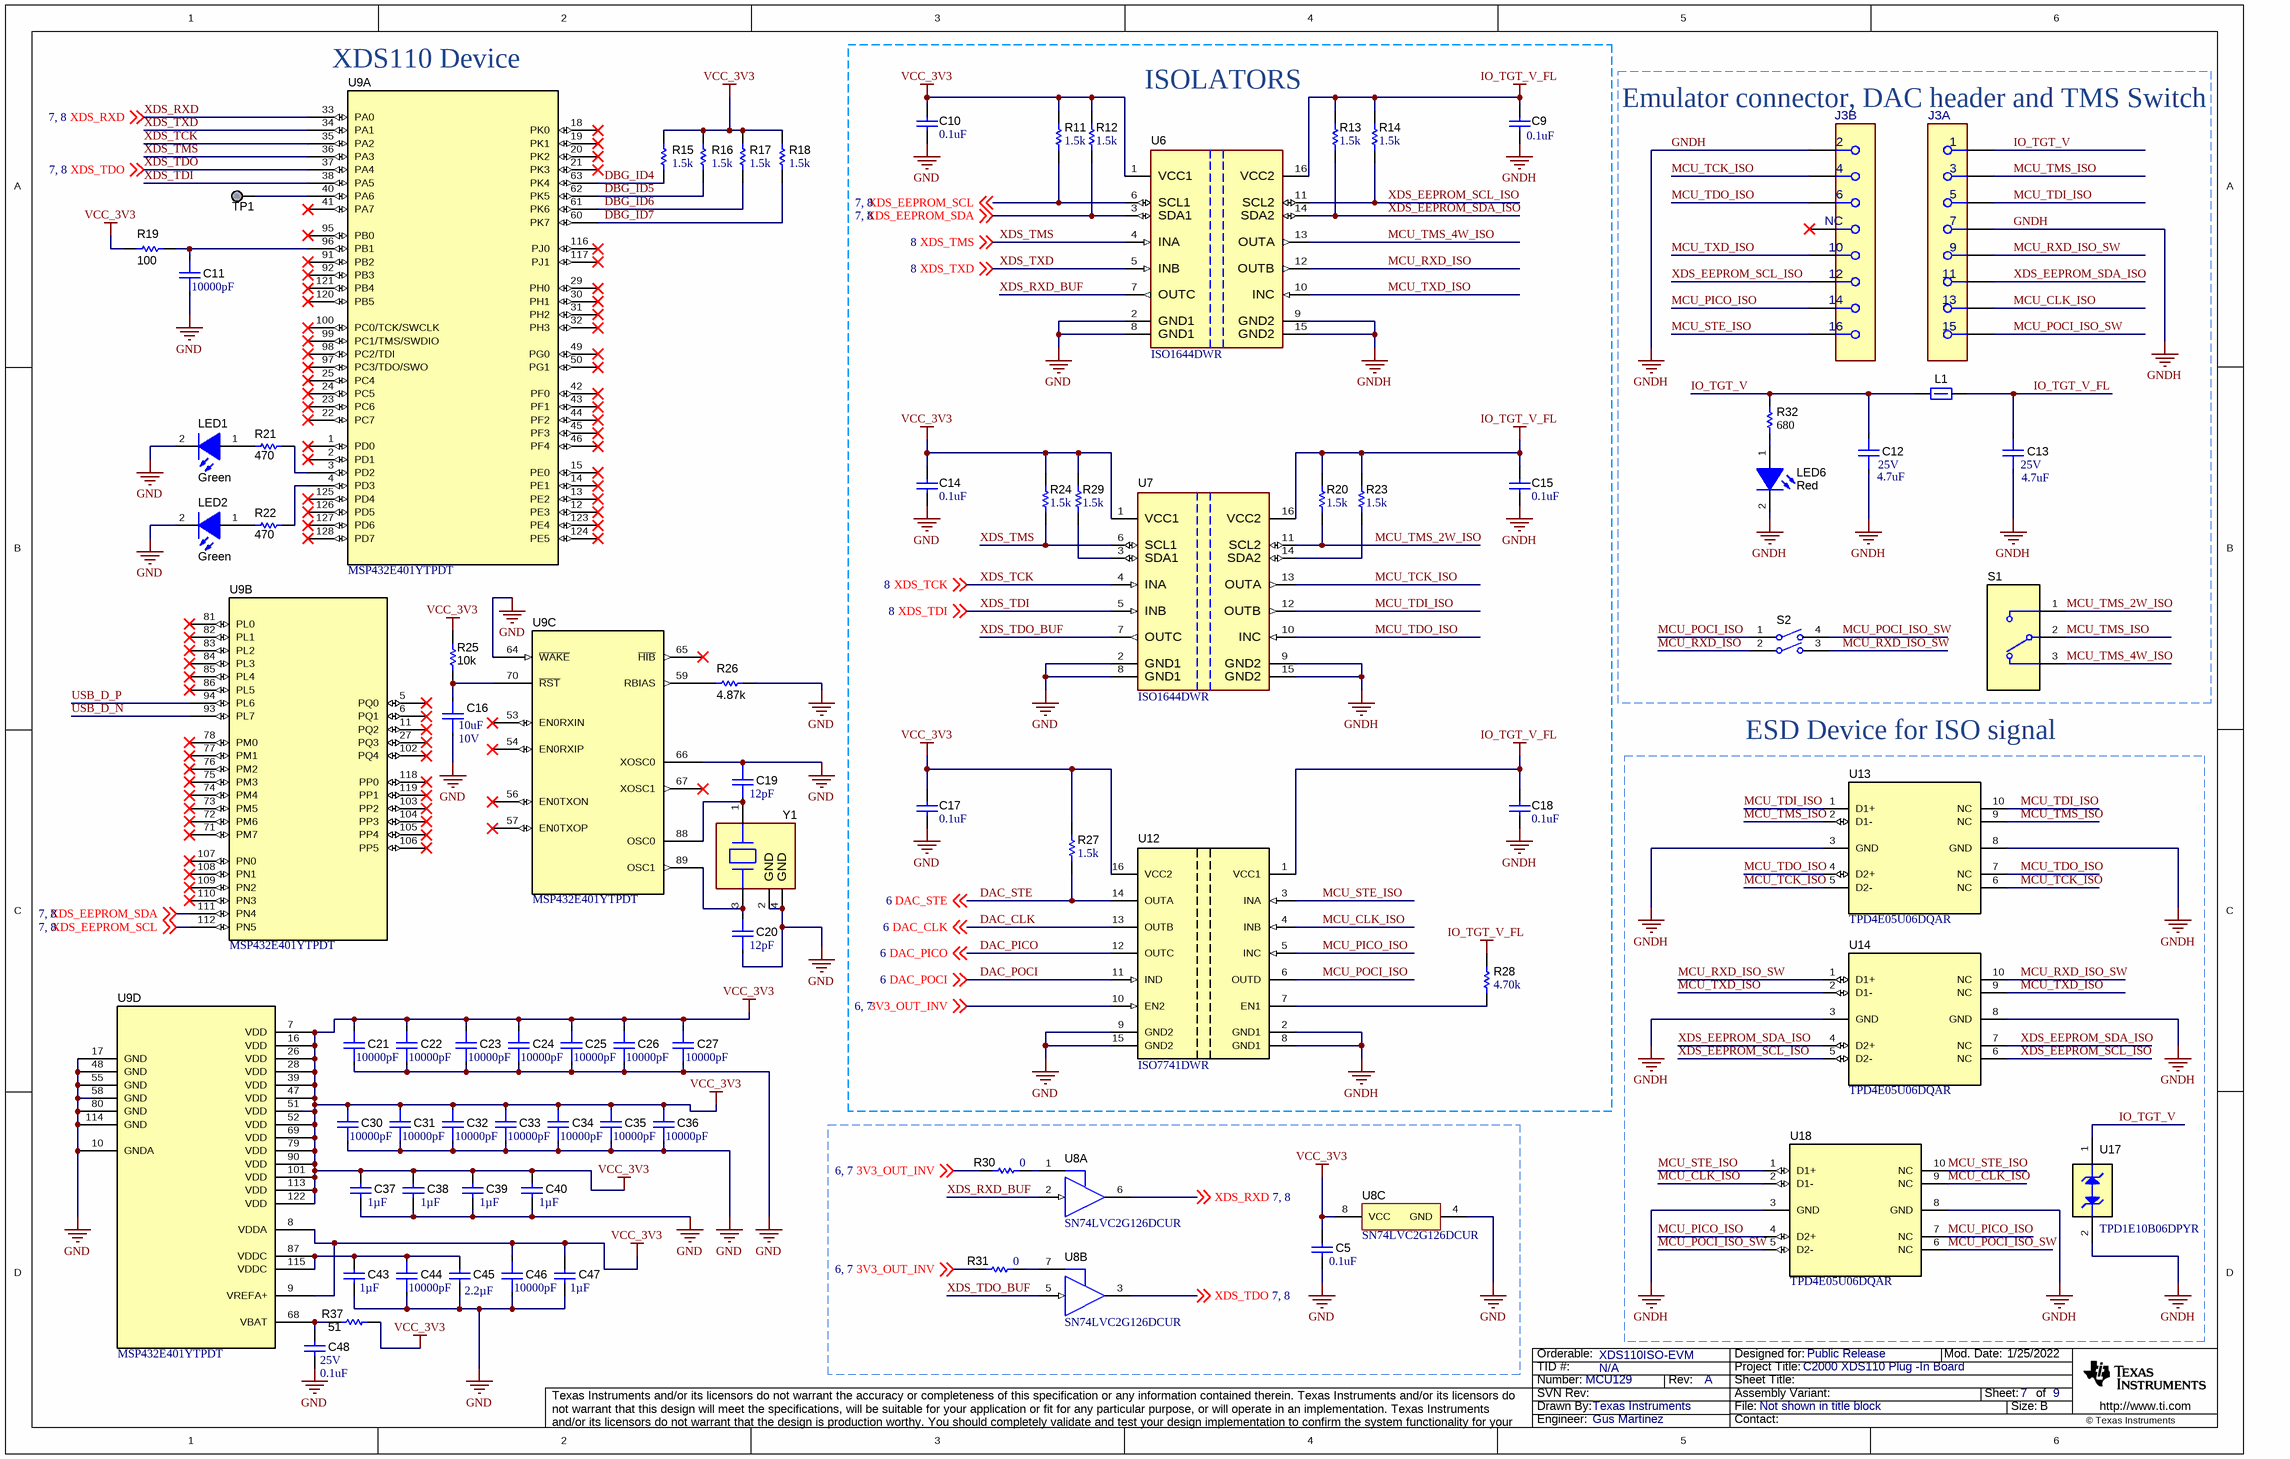
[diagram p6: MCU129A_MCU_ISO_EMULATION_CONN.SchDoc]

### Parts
C5  ValueDisplayed: 0.1uF  [0402]  (hidden comment: GRM155R71E104KE14D)
C9  ValueDisplayed: 0.1uF  [0402]  (hidden comment: GRM155R71E104KE14D)
C10  ValueDisplayed: 0.1uF  [0402]  (hidden comment: GRM155R71E104KE14D)
C11  ValueDisplayed: 10000pF  [FP-GRM1555C1E103JE01D_0402-MFG]  (hidden comment: GRM1555C1E103JE01D)
C12  VDC_V: 25V  ValueDisplayed: 4.7uF  [FP-GRM155C61E475ME15D_0402-MFG]  (hidden comment: GRM155C61E475ME15D)
C13  VDC_V: 25V  ValueDisplayed: 4.7uF  [FP-GRM155C61E475ME15D_0402-MFG]  (hidden comment: GRM155C61E475ME15D)
C14  ValueDisplayed: 0.1uF  [0402]  (hidden comment: GRM155R71E104KE14D)
C15  ValueDisplayed: 0.1uF  [0402]  (hidden comment: GRM155R71E104KE14D)
C16  ValueDisplayed: 10uF  VDC_V: 10V  [FP-GRM155R61A106ME18D_0402-MFG]  (hidden comment: GRM155R61A106ME18D)
C17  ValueDisplayed: 0.1uF  [0402]  (hidden comment: GRM155R71E104KE14D)
C18  ValueDisplayed: 0.1uF  [0402]  (hidden comment: GRM155R71E104KE14D)
C19  ValueDisplayed: 12pF  [FP-GRT1555C1H120JA02D_0402-MFG]  (hidden comment: GRT1555C1H120JA02D)
C20  ValueDisplayed: 12pF  [FP-GRT1555C1H120JA02D_0402-MFG]  (hidden comment: GRT1555C1H120JA02D)
C21  ValueDisplayed: 10000pF  [FP-GRM1555C1E103JE01D_0402-MFG]  (hidden comment: GRM1555C1E103JE01D)
C22  ValueDisplayed: 10000pF  [FP-GRM1555C1E103JE01D_0402-MFG]  (hidden comment: GRM1555C1E103JE01D)
C23  ValueDisplayed: 10000pF  [FP-GRM1555C1E103JE01D_0402-MFG]  (hidden comment: GRM1555C1E103JE01D)
C24  ValueDisplayed: 10000pF  [FP-GRM1555C1E103JE01D_0402-MFG]  (hidden comment: GRM1555C1E103JE01D)
C25  ValueDisplayed: 10000pF  [FP-GRM1555C1E103JE01D_0402-MFG]  (hidden comment: GRM1555C1E103JE01D)
C26  ValueDisplayed: 10000pF  [FP-GRM1555C1E103JE01D_0402-MFG]  (hidden comment: GRM1555C1E103JE01D)
C27  ValueDisplayed: 10000pF  [FP-GRM1555C1E103JE01D_0402-MFG]  (hidden comment: GRM1555C1E103JE01D)
C30  ValueDisplayed: 10000pF  [FP-GRM1555C1E103JE01D_0402-MFG]  (hidden comment: GRM1555C1E103JE01D)
C31  ValueDisplayed: 10000pF  [FP-GRM1555C1E103JE01D_0402-MFG]  (hidden comment: GRM1555C1E103JE01D)
C32  ValueDisplayed: 10000pF  [FP-GRM1555C1E103JE01D_0402-MFG]  (hidden comment: GRM1555C1E103JE01D)
C33  ValueDisplayed: 10000pF  [FP-GRM1555C1E103JE01D_0402-MFG]  (hidden comment: GRM1555C1E103JE01D)
C34  ValueDisplayed: 10000pF  [FP-GRM1555C1E103JE01D_0402-MFG]  (hidden comment: GRM1555C1E103JE01D)
C35  ValueDisplayed: 10000pF  [FP-GRM1555C1E103JE01D_0402-MFG]  (hidden comment: GRM1555C1E103JE01D)
C36  ValueDisplayed: 10000pF  [FP-GRM1555C1E103JE01D_0402-MFG]  (hidden comment: GRM1555C1E103JE01D)
C37  ValueDisplayed: 1µF  [0402]  (hidden comment: GRM155R61E105KE11D)
C38  ValueDisplayed: 1µF  [0402]  (hidden comment: GRM155R61E105KE11D)
C39  ValueDisplayed: 1µF  [0402]  (hidden comment: GRM155R61E105KE11D)
C40  ValueDisplayed: 1µF  [0402]  (hidden comment: GRM155R61E105KE11D)
C43  ValueDisplayed: 1µF  [0402]  (hidden comment: GRM155R61E105KE11D)
C44  ValueDisplayed: 10000pF  [FP-GRM1555C1E103JE01D_0402-MFG]  (hidden comment: GRM1555C1E103JE01D)
C45  ValueDisplayed: 2.2µF  [0402]  (hidden comment: GRM155R61E225ME15D)
C46  ValueDisplayed: 10000pF  [FP-GRM1555C1E103JE01D_0402-MFG]  (hidden comment: GRM1555C1E103JE01D)
C47  ValueDisplayed: 1µF  [0402]  (hidden comment: GRM155R61E105KE11D)
C48  ValueDisplayed: 0.1uF  Value2: 25V  [0402]  (hidden comment: GRM155R71E104KE14D)
J3  SSW-108-02-G-D-RA-008  [FP-SSW-108-02-G-D-RA-008_CONN_RCPT15-MFG]  (value not drawn)  (parts A,B of 2)
L1  BLM15BD121SN1D  [0402]  (value not drawn)
LED1  value Green  [APHHS1005_Green]  (hidden comment: APHHS1005CGCK)
LED2  value Green  [APHHS1005_Green]  (hidden comment: APHHS1005CGCK)
LED6  value Red  [APHHS1005_Red]  (hidden comment: APHHS1005SURCK)
R11  ValueDisplayed: 1.5k  [0402]  (hidden comment: CRCW04021K50JNED)
R12  ValueDisplayed: 1.5k  [0402]  (hidden comment: CRCW04021K50JNED)
R13  ValueDisplayed: 1.5k  [0402]  (hidden comment: CRCW04021K50JNED)
R14  ValueDisplayed: 1.5k  [0402]  (hidden comment: CRCW04021K50JNED)
R15  ValueDisplayed: 1.5k  [0402]  (hidden comment: CRCW04021K50JNED)
R16  ValueDisplayed: 1.5k  [0402]  (hidden comment: CRCW04021K50JNED)
R17  ValueDisplayed: 1.5k  [0402]  (hidden comment: CRCW04021K50JNED)
R18  ValueDisplayed: 1.5k  [0402]  (hidden comment: CRCW04021K50JNED)
R19  ValueDisplayed: 100  [0402]  (hidden comment: CRCW0402100RJNED)
R20  ValueDisplayed: 1.5k  [0402]  (hidden comment: CRCW04021K50JNED)
R21  ValueDisplayed: 470  [0402]  (hidden comment: RC0402FR-07470RL)
R22  ValueDisplayed: 470  [0402]  (hidden comment: RC0402FR-07470RL)
R23  ValueDisplayed: 1.5k  [0402]  (hidden comment: CRCW04021K50JNED)
R24  ValueDisplayed: 1.5k  [0402]  (hidden comment: CRCW04021K50JNED)
R25  ValueDisplayed: 10k  [0402]  (hidden comment: CRCW040210K0JNED)
R26  ValueDisplayed: 4.87k  [0402]  (hidden comment: CRCW04024K87FKED)
R27  ValueDisplayed: 1.5k  [0402]  (hidden comment: CRCW04021K50JNED)
R28  ValueDisplayed: 4.70k  [0402]  (hidden comment: CRG0402F4K7)
R29  ValueDisplayed: 1.5k  [0402]  (hidden comment: CRCW04021K50JNED)
R30  ValueDisplayed: 0  [0402]  (hidden comment: CRCW04020000Z0ED)
R31  ValueDisplayed: 0  [0402]  (hidden comment: CRCW04020000Z0ED)
R32  ValueDisplayed: 680  [0402]  (hidden comment: CRCW0402680RJNED)
R37  ValueDisplayed: 51  [0402]  (hidden comment: CRCW040251R0JNED)
S1  CAS-120TA  [SW_CAS-120TA]  (value not drawn)
S2  218-2LPST  [SW_218-2LP]  (value not drawn)
TP1  TP_SM_1MM  [TP_SM_1MM]  (value not drawn)  (no BOM)
U6  ISO1644DWR  [DW0016B-MFG]
U7  ISO1644DWR  [DW0016B-MFG]
U8  SN74LVC2G126DCUR  [DCU0008A_N]  (parts A,B,C of 3)
U9  MSP432E401YTPDT  [PDT0128A]  (parts A,B,C,D of 4)
U12  ISO7741DWR  [DW0016B_HV]
U13  TPD4E05U06DQAR  [DQA0010A]
U14  TPD4E05U06DQAR  [DQA0010A]
U17  TPD1E10B06DPYR  [DPY0002A]
U18  TPD4E05U06DQAR  [DQA0010A]
Y1  830064296  [FP-830064296_SMT4_3MM4_2MM7-MFG]  (value not drawn)

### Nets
GND: C5.1 C10.2 C11.1 C14.2 C16.1 C17.2 C19.1 C20.1 C21.1 C22.1 C23.1 C24.1 C25.1 C26.1 C27.1 C30.1 C31.1 C32.1 C33.1 C34.1 C35.1 C36.1 C37.2 C38.2 C39.2 C40.2 C43.2 C44.1 C45.2 C46.1 C47.2 C48.1 LED1.2(K) LED2.2(K) R26.1 U6.2(GND1) U6.8(GND1) U7.2(GND1) U7.8(GND1) U8.4(GND) U9.10(GNDA) U9.17(GND) U9.48(GND) U9.55(GND) U9.58(GND) U9.64(~{WAKE}) U9.66(XOSC0) U9.80(GND) U9.114(GND) U12.9(GND2) U12.15(GND2) Y1.2(GND) Y1.4(GND)
GNDH: C9.1 C12.1 C13.1 C15.1 C18.1 J3.2 J3.7 LED6.2(K) U6.9(GND2) U6.15(GND2) U7.9(GND2) U7.15(GND2) U12.2(GND1) U12.8(GND1) U13.3(GND) U13.8(GND) U14.3(GND) U14.8(GND) U17.2(A) U18.3(GND) U18.8(GND)
IO_TGT_V_FL: C9.2 C13.2 C15.2 C18.2 L1.2 R13.2 R14.2 R20.2 R23.2 R28.2 U6.16(VCC2) U7.16(VCC2) U12.1(VCC1)
VCC_3V3: C5.2 C10.1 C14.1 C17.1 C21.2 C22.2 C23.2 C24.2 C25.2 C26.2 C27.2 C30.2 C31.2 C32.2 C33.2 C34.2 C35.2 C36.2 C37.1 C38.1 C39.1 C40.1 C46.2 C47.1 R11.2 R12.2 R15.1 R16.1 R17.1 R18.1 R19.1 R24.2 R25.2 R27.2 R29.2 R37.2 U6.1(VCC1) U7.1(VCC1) U8.8(VCC) U9.7(VDD) U9.8(VDDA) U9.9(VREFA+) U9.16(VDD) U9.26(VDD) U9.28(VDD) U9.39(VDD) U9.47(VDD) U9.51(VDD) U9.52(VDD) U9.69(VDD) U9.79(VDD) U9.90(VDD) U9.101(VDD) U9.113(VDD) U9.122(VDD) U12.16(VCC2)
3V3_OUT_INV: R30.2 R31.2 U12.10(EN2) ; off-sheet 3V3_OUT_INV
DAC_CLK: U12.13(OUTB) ; off-sheet DAC_CLK
DAC_PICO: U12.12(OUTC) ; off-sheet DAC_PICO
DAC_POCI: U12.11(IND) ; off-sheet DAC_POCI
DAC_STE: R27.1 U12.14(OUTA) ; off-sheet DAC_STE
DBG_ID4: R15.2 U9.63(PK4)
DBG_ID5: R16.2 U9.62(PK5)
DBG_ID6: R17.2 U9.61(PK6)
DBG_ID7: R18.2 U9.60(PK7)
IO_TGT_V: C12.2 J3.1 L1.1 R32.2 U17.1(K)
MCU_CLK_ISO: J3.13 U12.4(INB) U18.2(D1-) U18.9(NC)
MCU_PICO_ISO: J3.14 U12.5(INC) U18.4(D2+) U18.7(NC)
MCU_POCI_ISO: S2.1 U12.6(OUTD)
MCU_POCI_ISO_SW: J3.15 S2.4 U18.5(D2-) U18.6(NC)
MCU_RXD_ISO: S2.2 U6.12(OUTB)
MCU_RXD_ISO_SW: J3.9 S2.3 U14.1(D1+) U14.10(NC)
MCU_STE_ISO: J3.16 U12.3(INA) U18.1(D1+) U18.10(NC)
MCU_TCK_ISO: J3.4 U7.13(OUTA) U13.5(D2-) U13.6(NC)
MCU_TDI_ISO: J3.5 U7.12(OUTB) U13.1(D1+) U13.10(NC)
MCU_TDO_ISO: J3.6 U7.10(INC) U13.4(D2+) U13.7(NC)
MCU_TMS_2W_ISO: R20.1 S1.1 U7.11(SCL2)
MCU_TMS_4W_ISO: S1.3 U6.13(OUTA)
MCU_TMS_ISO: J3.3 S1.2 U13.2(D1-) U13.9(NC)
MCU_TXD_ISO: J3.10 U6.10(INC) U14.2(D1-) U14.9(NC)
USB_D_N: U9.93(PL7)
USB_D_P: U9.94(PL6)
XDS_EEPROM_SCL: R11.1 U6.6(SCL1) U9.112(PN5) ; off-sheet XDS_EEPROM_SCL
XDS_EEPROM_SCL_ISO: J3.12 R14.1 U6.11(SCL2) U14.5(D2-) U14.6(NC)
XDS_EEPROM_SDA: R12.1 U6.3(SDA1) U9.111(PN4) ; off-sheet XDS_EEPROM_SDA
XDS_EEPROM_SDA_ISO: J3.11 R13.1 U6.14(SDA2) U14.4(D2+) U14.7(NC)
XDS_RXD: U8.6(1Y) U9.33(PA0) ; off-sheet XDS_RXD
XDS_RXD_BUF: U6.7(OUTC) U8.2(1A)
XDS_TCK: U7.4(INA) U9.35(PA2) ; off-sheet XDS_TCK
XDS_TDI: U7.5(INB) U9.38(PA5) ; off-sheet XDS_TDI
XDS_TDO: U8.3(2Y) U9.37(PA4) ; off-sheet XDS_TDO
XDS_TDO_BUF: U7.7(OUTC) U8.5(2A)
XDS_TMS: R24.1 U6.4(INA) U7.6(SCL1) U9.36(PA3) ; off-sheet XDS_TMS
XDS_TXD: U6.5(INB) U9.34(PA1) ; off-sheet XDS_TXD
NetC11_2: C11.2 R19.2 U9.96(PB1)
NetC16_2: C16.2 R25.1 U9.70(~{RST})
NetC19_2: C19.2 U9.88(OSC0) Y1.1(1_Crystal)
NetC20_2: C20.2 U9.89(OSC1) Y1.3(2_Crystal)
NetC43_1: C43.1 C44.2 C45.1 U9.87(VDDC) U9.115(VDDC)
NetC48_2: C48.2 R37.1 U9.68(VBAT)
NetLED1_1: LED1.1(A) R21.1
NetLED2_1: LED2.1(A) R22.1
NetLED6_1: LED6.1(A) R32.1
NetR21_2: R21.2 U9.3(PD2)
NetR22_2: R22.2 U9.4(PD3)
NetR23_1: R23.1 U7.14(SDA2)
NetR26_2: R26.2 U9.59(RBIAS)
NetR28_1: R28.1 U12.7(EN1)
NetR29_1: R29.1 U7.3(SDA1)
NetR30_1: R30.1 U8.1(1OE)
NetR31_1: R31.1 U8.7(2OE)
NetTP1_1: TP1.1 U9.40(PA6)

Not connected (* = marked no-connect by the designer): J3 8(NC)*; U9 1(PD0)* 2(PD1)* 5(PQ0)* 6(PQ1)* 11(PQ2)* 12(PE3)* 13(PE2)* 14(PE1)* 15(PE0)* 18(PK0)* 19(PK1)* 20(PK2)* 21(PK3)* 22(PC7)* 23(PC6)* 24(PC5)* 25(PC4)* 27(PQ3)* 29(PH0)* 30(PH1)* 31(PH2)* 32(PH3)* 41(PA7)* 42(PF0)* 43(PF1)* 44(PF2)* 45(PF3)* 46(PF4)* 49(PG0)* 50(PG1)* 53(EN0RXIN)* 54(EN0RXIP)* 56(EN0TXON)* 57(EN0TXOP)* 65(~{HIB})* 67(XOSC1)* 71(PM7)* 72(PM6)* 73(PM5)* 74(PM4)* 75(PM3)* 76(PM2)* 77(PM1)* 78(PM0)* 81(PL0)* 82(PL1)* 83(PL2)* 84(PL3)* 85(PL4)* 86(PL5)* 91(PB2)* 92(PB3)* 95(PB0)* 97(PC3/TDO/SWO)* 98(PC2/TDI)* 99(PC1/TMS/SWDIO)* 100(PC0/TCK/SWCLK)* 102(PQ4)* 103(PP2)* 104(PP3)* 105(PP4)* 106(PP5)* 107(PN0)* 108(PN1)* 109(PN2)* 110(PN3)* 116(PJ0)* 117(PJ1)* 118(PP0)* 119(PP1)* 120(PB5)* 121(PB4)* 123(PE4)* 124(PE5)* 125(PD4)* 126(PD5)* 127(PD6)* 128(PD7)*

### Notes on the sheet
- (near U9) XDS110 Device
- (near J3) Emulator connector, DAC header and TMS Switch
- (near R13) ISOLATORS
- ESD Device for ISO signal

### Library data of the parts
C5 C9 C10 C14 C15 C17 C18 = CMP-0006659-2: CAP, CERM, 0.1 uF, 25 V, +/- 10%, X7R, 0402; Manufacturer: MuRata; Polarized: N; Value: 0.1uF; U/M: EA; Cap_F: 100nF; Value1: Unknown; VDC_V: 25V; TaMin_C: -55°C; TaMax_C: 125°C; SizeArea_mm2: 0.5; SizeAreaWB_mm2: 3; SizeX_mm: 1; SizeZ_mm: 0.6; AEC Category: Q200
C11 C21-C27 C30-C36 C44 C46 = CMP-0035343-1: Chip Multilayer Ceramic Capacitors for General Purpose, 0402, 10000pF, C0G, 30ppm/°C, 5%, 25V; Manufacturer: Murata; Value: 10nF; SizeZ_mm: 0.65mm; AEC Qualified: No
C12 C13 = CMP-0120206-1: as C51 on sheet MCU129A_POWER_DAC_SECTION
C16 = CMP-0120207-1: 10 µF ±20% 10V Ceramic Capacitor X5R 0402 (1005 Metric); Manufacturer: Murata; AEC Qualified: No; Cap_F: 10µF; SizeZ_mm: 0.7mm; TempCo: 15%; Value: 10µF
C19 C20 = CMP-0120209-1: Multi-Layer Ceramic Capacitor 12pF 50V C0G ±5% 0402 Paper T/R; Manufacturer: Murata; TempCo: 30ppm/°C; SizeZ_mm: 0.55mm; AEC Qualified: Yes; AEC Grade: Grade 1
C37-C40 C43 C47 = CMP-0086061-1: CAP, CERM, 1 µF, 25 V,+/- 10%, X5R, 0402; Manufacturer: MuRata; Polarized: N; Value: 1uF; U/M: EA; VDC_V: 25V; TaMin_C: -55°C; TaMax_C: 85°C; SizeArea_mm2: 0.5; SizeAreaWB_mm2: 3; SizeX_mm: 1; SizeZ_mm: 0.6; AEC Category: Q200
C45 = CMP-0081010-1: CAP, CERM, 2.2 µF, 25 V,+/- 20%, X5R, 0402; Manufacturer: MuRata; TaMin_C: -55°C; Polarized: N; SizeAreaWB_mm2: 3; U/M: EA; Value: 2.2uF; TaMax_C: 85°C; SizeZ_mm: 0.6; SizeX_mm: 1; SizeY_mm: 0.5; Value2: 25V; AEC Category: Q200
C48 = CMP-0006659-2: as C53 on sheet MCU129A_POWER_DAC_SECTION
J3 = CMP-0122457-1: Conn Socket Strip SKT 16 POS 2.54mm Solder RA Thru-Hole; Manufacturer: Samtec; ContactFinish: Gold,Nickel; Current_A: 4.7A; Row_Count: 2; Voltage_V: 655V; AEC Qualified: No; Conn Gender: Female; Conn Orientation: Right Angle; Is Female: yes; SizeZ_mm: 5.08mm
L1 = CMP-0003333-1: Ferrite Bead, 120 ohm @ 100 MHz, 0.3 A, 0402; Manufacturer: MuRata; ZTyp@100MHz_Ohm: 120; SizeAreaWB_mm2: 3; DCR_ohm: 3d; Value1: 0.3 ohm; Value: 120 ohm; Imax_A: 3dA; SizeZ_mm: 0.6; SizeX_mm: 1; SizeY_mm: 0.5; Value2: 0.3A
LED1 LED2 = CMP-0067682-2: as LED5 on sheet MCU129A_POWER_DAC_SECTION
LED6 = CMP-0067681-2: as LED3 on sheet MCU129A_POWER_DAC_SECTION
R11-R18 R20 R23 R24 R27 R29 = CMP-0026856-5: as R50 on sheet MCU129A_POWER_DAC_SECTION
R19 = CMP-0026824-3: RES, 100, 5%, 0.063 W, AEC-Q200 Grade 0, 0402; Manufacturer: Vishay-Dale; Value: 100; Value_Code: 100R; Power_W: 63mW; Value2: 0.063W; VDC_V: 50V; TempCo: 200 ppm/C; SizeArea_mm2: 0.5; SizeX_mm: 1; SizeZ_mm: 0.6; EIA_Code: E24; AEC Category: Q200; AEC Qualified: Y; AEC Grade: 0
R21 R22 = CMP-0026736-1: RES, 470, 1%, 0.063 W, 0402; Manufacturer: Yageo America; Power_W: 63mW; TempCo: 100 ppm/C; Value_Code: 470R; U/M: EA; Value: 470; SizeX_mm: 1; SizeY_mm: 0.5; SizeZ_mm: 0.6; Value2: 0.063W; AEC Qualified: N; VDC_V: 50V; AEC Category: Q200
R25 = CMP-0026825-5: RES, 10 k, 5%, 0.063 W, AEC-Q200 Grade 0, 0402; Manufacturer: Vishay-Dale; Value: 10k; Value_Code: 10k0; Power_W: 63mW; Value2: 0.063W; VDC_V: 50V; TempCo: 200 ppm/C; SizeArea_mm2: 0.5; SizeX_mm: 1; SizeZ_mm: 0.6; EIA_Code: E24; AEC Category: Q200; AEC Qualified: Y; AEC Grade: 0
R26 = CMP-0026413-2: RES, 4.87 k, 1%, 0.063 W, AEC-Q200 Grade 0, 0402; Manufacturer: Vishay-Dale; Value: 4.87k; Value_Code: 4k87; Power_W: 63mW; Value2: 0.063W; VDC_V: 50V; TempCo: 100 ppm/C; SizeArea_mm2: 0.5; SizeX_mm: 1; SizeZ_mm: 0.6; EIA_Code: E96; AEC Category: Q200; AEC Qualified: Y; AEC Grade: 0
R28 = CMP-0026631-1: as R47 on sheet MCU129A_POWER_DAC_SECTION
R30 R31 = CMP-0026822-3: as R38 on sheet MCU129A_POWER_DAC_SECTION
R32 = CMP-0026962-3: as R41 on sheet MCU129A_POWER_DAC_SECTION
R37 = CMP-0026946-3: RES, 51, 5%, 0.063 W, AEC-Q200 Grade 0, 0402; Manufacturer: Vishay-Dale; Value: 51; Value_Code: 51R0; Power_W: 63mW; Value2: 0.063W; VDC_V: 50V; TempCo: 200 ppm/C; SizeArea_mm2: 0.5; SizeX_mm: 1; SizeZ_mm: 0.6; EIA_Code: E24; AEC Category: Q200; AEC Qualified: Y; AEC Grade: 0
S1 = CMP-0002139-2: Switch, Slide, SPDT  100mA, SMT; Manufacturer: Copal Electronics; CurrentRating_mA: 100A; SwitchFunction: On-On; VDC_V: 6V; PositionCount: 1
S2 = CMP-0002230-1: Switch, SPST, 2 Pos, 25mA, 24VDC, SMD; Manufacturer: CTS Electrocomponents; CurrentRating_mA: 25A; PositionCount: 2; VDC_V: 24V; SwitchFunction: Off-On
TP1 = CMP-0003825-1: 1mm Test Point, SMT; Manufacturer: Any
U6 U7 = CMP-0091558-3: Hot-swappable bidirectional I2C isolator with GPIO and enhanced EMC; Manufacturer: Texas Instruments; CompType: IC; Standoff Height: 0.1mm; SizeZ_mm: 2.65mm; AEC Category: Q200
U8 = CMP-0051824-2: Dual Bus Buffer Gate With 3-State Outputs, DCU0008A (VSSOP-8); Manufacturer: Texas Instruments; Logic: True; Voltage(Nom)(V): 1.8,2.5,3.3,5; Input Type: CMOS/TTL; ICC @ Nom Voltage(Max)(mA): 0.01; VCC(Min)(V): 1.65; Bits(#): 2; tpd @ Nom Voltage(Max)(ns): 9.8,4.9,4,3.2; 3-State Output: Yes; Technology Family: LVC; Rating: Catalog; Output Drive (IOL/IOH)(Max)(mA): 32/-32; Schmitt Trigger: No; Output Type: CMOS; F @ Nom Voltage(Max)(Mhz): 150; VCC(Max)(V): 5.5; AEC Category: Q200; AEC Qualified: N; CompType: IC; SizeAreaWB_mm2: 12.6; SizeArea_mm2: 6.4; SizeX_mm: 3.2; SizeY_mm: 2.0; SizeZ_mm: 0.9
U9 = CMP-0077953-1: MSP432E401YTPDT, PDT0128A (TQFP-128); Alternate PartNumber: MSP432E401YTPDTR; Alternate Manufacturer: Texas Instruments; SizeAreaWB_mm2: 324; SizeZ_mm: 1.2; SizeX_mm: 16; SizeArea_mm2: 256; CompType: IC; AEC Qualified: N; AEC Category: Q200
U12 = CMP-0076064-3: High-Speed, Low-Power, Robust EMC Quad-Channel Digital Isolator, DW0016B (SOIC-16); Manufacturer: Texas Instruments; Green_Lifecycle: Active; AEC Category: Q200; CompType: IC; Green_REACh: Passed; SizeAreaWB_mm2: 152.52; SizeX_mm: 10.4; Rating: Catalog; SizeY_mm: 10.3; AEC Qualified: N; SizeZ_mm: 2.65; SizeArea_mm2: 107.12
U13 U14 U18 = CMP-0073613-3: as U24 on sheet MCU129A_POWER_DAC_SECTION
U17 = CMP-0043093-4: as U22 on sheet MCU129A_POWER_DAC_SECTION
Y1 = CMP-0094478-1: Crystal 16 MHz ±20ppm Crystal 8pF 70 Ohms 4-SMD, No Lead; Manufacturer: Wurth; SizeZ_mm: 0.8mm; Frequency_Fixed: 16MHz; Esr: 70

## Sheet MCU129A_HIGH_DENSITY_CONN.SchDoc
size 431 x 279 mm; Date: Not shown in title block; ApprovedBy: Not shown in title block; CheckedBy: Not shown in title block; Author: Not shown in title block; CompanyName: Not shown in title block; Engineer: Not shown in title block; Organization: Not shown in title block; Address1: Not shown in title block; Address2: Not shown in title block; Address3: Not shown in title block; Address4: Not shown in title block; DocumentNumber: 8; Revision: Use project parameter SCH_Rev; SheetNumber: 8; SheetTotal: 9; PageSetup: Record=PageOptions¦CenterHorizontal=True¦CenterVertical=True¦PrintScale=1.00¦XCorrection=1.00¦YCorrection=1.00¦PrintKind=0¦BorderSize=5000000¦LeftOffset=0¦BottomOffset=0¦Orientation=2¦PaperLength=1000¦PaperWidth=1000¦Scale=100¦PaperSource=15¦PrintQuality=600¦MediaType=1¦DitherType=10¦PaperKind=Letter¦PrintScaleMode=1
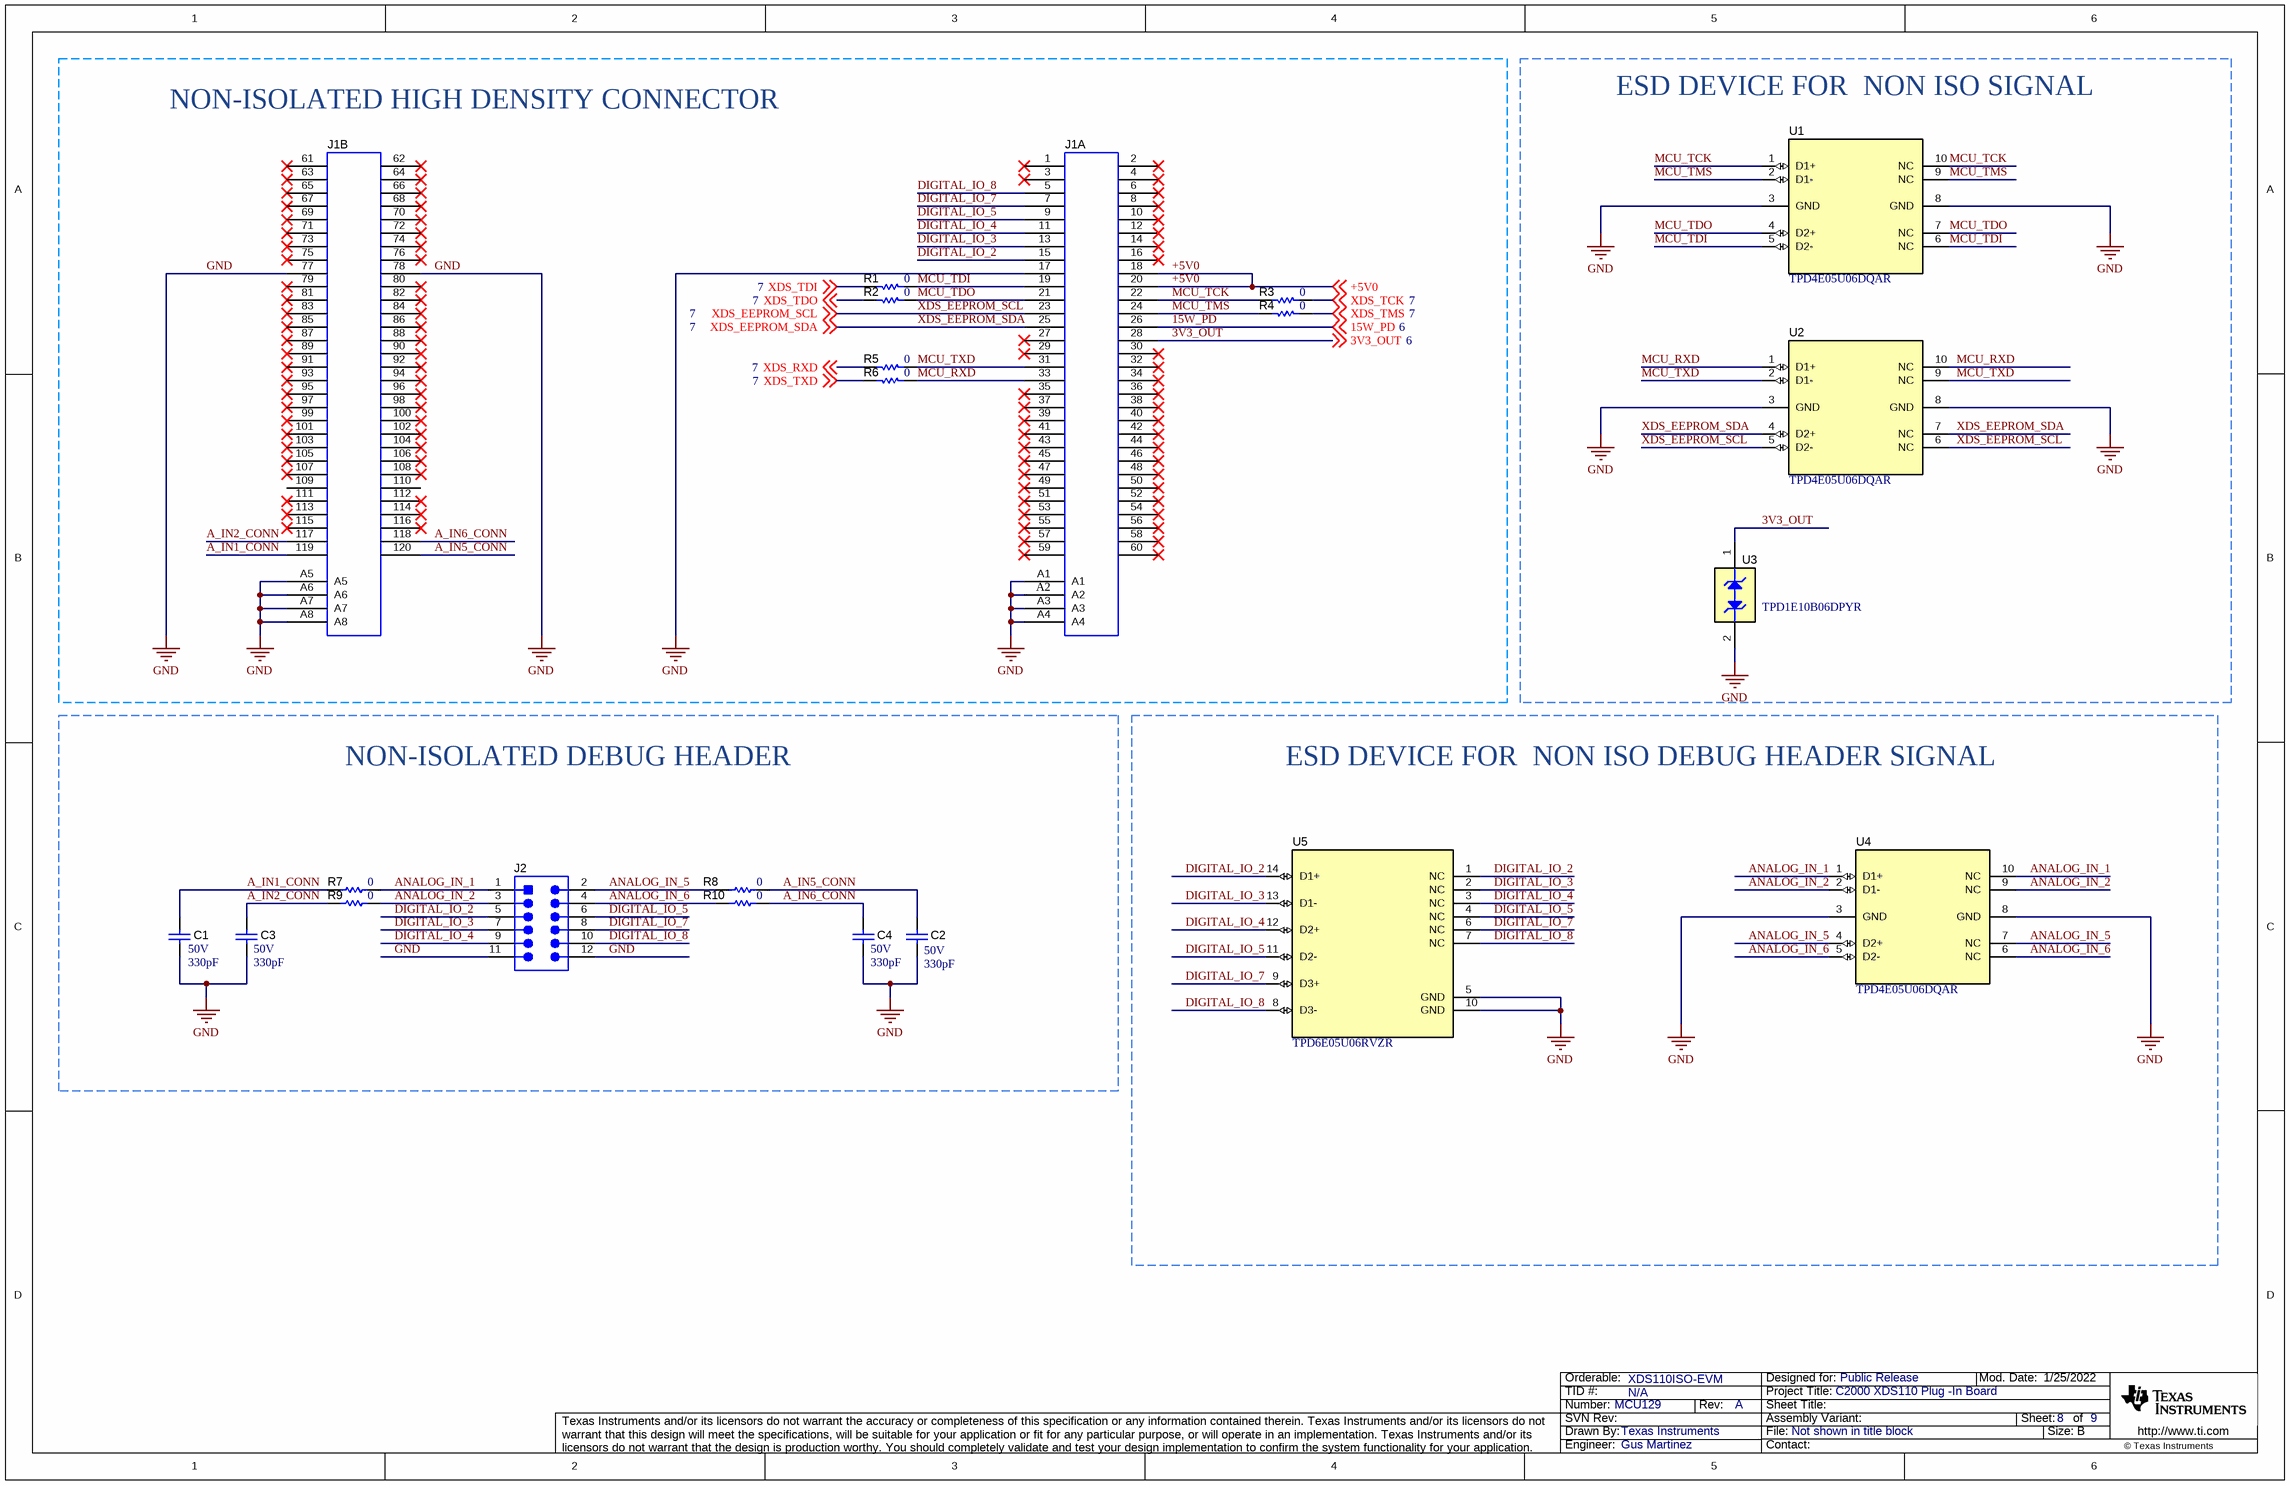
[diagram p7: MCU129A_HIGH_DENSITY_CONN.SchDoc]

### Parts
C1  VDC_V: 50V  ValueDisplayed: 330pF  [0402]  (hidden comment: GRM1555C1H331JA01D)
C2  VDC_V: 50V  ValueDisplayed: 330pF  [0402]  (hidden comment: GRM1555C1H331JA01D)
C3  VDC_V: 50V  ValueDisplayed: 330pF  [0402]  (hidden comment: GRM1555C1H331JA01D)
C4  VDC_V: 50V  ValueDisplayed: 330pF  [0402]  (hidden comment: GRM1555C1H331JA01D)
J1  QTH-060-01-L-D-A  [SAMTEC_QTH-060-01-L-D-A]  (value not drawn)  (parts A,B of 2)
J2  TSM-106-01-L-DV  [Samtec_TSM-106-01-x-DV]  (value not drawn)
R1  ValueDisplayed: 0  [0402]  (hidden comment: CRCW04020000Z0ED)
R2  ValueDisplayed: 0  [0402]  (hidden comment: CRCW04020000Z0ED)
R3  ValueDisplayed: 0  [0402]  (hidden comment: CRCW04020000Z0ED)
R4  ValueDisplayed: 0  [0402]  (hidden comment: CRCW04020000Z0ED)
R5  ValueDisplayed: 0  [0402]  (hidden comment: CRCW04020000Z0ED)
R6  ValueDisplayed: 0  [0402]  (hidden comment: CRCW04020000Z0ED)
R7  ValueDisplayed: 0  [0402]  (hidden comment: CRCW04020000Z0ED)
R8  ValueDisplayed: 0  [0402]  (hidden comment: CRCW04020000Z0ED)
R9  ValueDisplayed: 0  [0402]  (hidden comment: CRCW04020000Z0ED)
R10  ValueDisplayed: 0  [0402]  (hidden comment: CRCW04020000Z0ED)
U1  TPD4E05U06DQAR  [DQA0010A]
U2  TPD4E05U06DQAR  [DQA0010A]
U3  TPD1E10B06DPYR  [DPY0002A]
U4  TPD4E05U06DQAR  [DQA0010A]
U5  TPD6E05U06RVZR  [RVZ0014A]

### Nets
+5V0: J1.18 J1.20 ; off-sheet +5V0
GND: C1.1 C2.2 C3.2 C4.2 J1.17 J1.77 J1.78 J1.A1 J1.A2 J1.A3 J1.A4 J1.A5 J1.A6 J1.A7 J1.A8 J2.11 J2.12 U1.3(GND) U1.8(GND) U2.3(GND) U2.8(GND) U3.2(A) U4.3(GND) U4.8(GND) U5.5(GND) U5.10(GND)
3V3_OUT: J1.28 U3.1(K) ; off-sheet 3V3_OUT
15W_PD: J1.26 ; off-sheet 15W_PD
A_IN1_CONN: C1.2 J1.119 R7.2
A_IN2_CONN: C3.1 J1.117 R9.2
A_IN5_CONN: C2.1 J1.120 R8.1
A_IN6_CONN: C4.1 J1.118 R10.1
ANALOG_IN_1: J2.1 R7.1 U4.1(D1+) U4.10(NC)
ANALOG_IN_2: J2.3 R9.1 U4.2(D1-) U4.9(NC)
ANALOG_IN_5: J2.2 R8.2 U4.4(D2+) U4.7(NC)
ANALOG_IN_6: J2.4 R10.2 U4.5(D2-) U4.6(NC)
DIGITAL_IO_2: J1.15 J2.5 U5.1(NC) U5.14(D1+)
DIGITAL_IO_3: J1.13 J2.7 U5.2(NC) U5.13(D1-)
DIGITAL_IO_4: J1.11 J2.9 U5.3(NC) U5.12(D2+)
DIGITAL_IO_5: J1.9 J2.6 U5.4(NC) U5.11(D2-)
DIGITAL_IO_7: J1.7 J2.8 U5.6(NC) U5.9(D3+)
DIGITAL_IO_8: J1.5 J2.10 U5.7(NC) U5.8(D3-)
MCU_RXD: J1.33 R6.2 U2.1(D1+) U2.10(NC)
MCU_TCK: J1.22 R3.1 U1.1(D1+) U1.10(NC)
MCU_TDI: J1.19 R1.2 U1.5(D2-) U1.6(NC)
MCU_TDO: J1.21 R2.2 U1.4(D2+) U1.7(NC)
MCU_TMS: J1.24 R4.1 U1.2(D1-) U1.9(NC)
MCU_TXD: J1.31 R5.2 U2.2(D1-) U2.9(NC)
XDS_EEPROM_SCL: J1.23 U2.5(D2-) U2.6(NC) ; off-sheet XDS_EEPROM_SCL
XDS_EEPROM_SDA: J1.25 U2.4(D2+) U2.7(NC) ; off-sheet XDS_EEPROM_SDA
XDS_RXD: R5.1 ; off-sheet XDS_RXD
XDS_TCK: R3.2 ; off-sheet XDS_TCK
XDS_TDI: R1.1 ; off-sheet XDS_TDI
XDS_TDO: R2.1 ; off-sheet XDS_TDO
XDS_TMS: R4.2 ; off-sheet XDS_TMS
XDS_TXD: R6.1 ; off-sheet XDS_TXD

Not connected (* = marked no-connect by the designer): J1 1* 2* 3* 4* 6* 8* 10* 12* 14* 16* 27* 29* 30* 32* 34* 35* 36* 37* 38* 39* 40* 41* 42* 43* 44* 45* 46* 47* 48* 49* 50* 51* 52* 53* 54* 55* 56* 57* 58* 59* 60* 61* 62* 63* 64* 65* 66* 67* 68* 69* 70* 71* 72* 73* 74* 75* 76* 79* 80* 81* 82* 83* 84* 85* 86* 87* 88* 89* 90* 91* 92* 93* 94* 95* 96* 97* 98* 99* 100* 101* 102* 103* 104* 105* 106* 107* 108* 109 110 111* 112* 113* 114* 115* 116*

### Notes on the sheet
- (near J1) NON-ISOLATED HIGH DENSITY CONNECTOR
- ESD DEVICE FOR  NON ISO SIGNAL
- NON-ISOLATED DEBUG HEADER
- ESD DEVICE FOR  NON ISO DEBUG HEADER SIGNAL

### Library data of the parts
C1-C4 = CMP-0006456-2: CAP, CERM, 330 pF, 50 V, +/- 5%, C0G/NP0, 0402; Manufacturer: MuRata; TaMin_C: -55°C; Polarized: N; SizeAreaWB_mm2: 3; Value1: Unknown; U/M: EA; Value: 330pF; TaMax_C: 125°C; SizeZ_mm: 0.6; SizeX_mm: 1; SizeY_mm: 0.5; AEC Category: Q200
J1 = CMP-0056023-2: Socket, 0.5MM, 60x2, Gold, SMT; Manufacturer: Samtec; Green_Lifecycle: Not Set; Green_REACh: Incomplete
J2 = CMP-0075594-2: Header, 2.54mm, 6x2, Gold, SMT; Manufacturer: Samtec; Pitch_mm: 2.54; Gender: Male; Cert_CSA: Y; Green_REACh: Passed; Current_A: 4.9A; Voltage_V: 475V; Shrouded: N; Green_Lifecycle: Active; Row_Count: 2
R1-R10 = CMP-0026822-3: as R38 on sheet MCU129A_POWER_DAC_SECTION
U1 U2 U4 = CMP-0073613-3: as U24 on sheet MCU129A_POWER_DAC_SECTION
U3 = CMP-0043093-4: as U22 on sheet MCU129A_POWER_DAC_SECTION
U5 = CMP-0073614-1: 6-Channel Ultra-Low-Capacitance IEC ESD Protection Diodes, RVZ0014A (USON-14); Alternate Manufacturer: Texas Instruments; Green_Lifecycle: Active; SizeAreaWB_mm2: 10.575; Green_REACh: Passed; U/M: EA; SizeZ_mm: 0.55; SizeX_mm: 1.35; SizeY_mm: 3.5; SizeArea_mm2: 4.725; CompType: IC

## Sheet MCU129A_EVM_Hardware.SchDoc
size 431 x 279 mm; Date: Not shown in title block; ApprovedBy: Not shown in title block; CheckedBy: Not shown in title block; Author: Not shown in title block; CompanyName: Not shown in title block; Engineer: Not shown in title block; Organization: Not shown in title block; Address1: Not shown in title block; Address2: Not shown in title block; Address3: Not shown in title block; Address4: Not shown in title block; DocumentNumber: 9; Revision: Use project parameter SCH_Rev; SheetNumber: 9; SheetTotal: 9; PageSetup: Record=PageOptions¦CenterHorizontal=True¦CenterVertical=True¦PrintScale=1.00¦XCorrection=1.00¦YCorrection=1.00¦PrintKind=0¦BorderSize=5000000¦LeftOffset=0¦BottomOffset=0¦Orientation=2¦PaperLength=1000¦PaperWidth=1000¦Scale=100¦PaperSource=15¦PrintQuality=600¦MediaType=1¦DitherType=10¦PaperKind=Letter¦PrintScaleMode=1
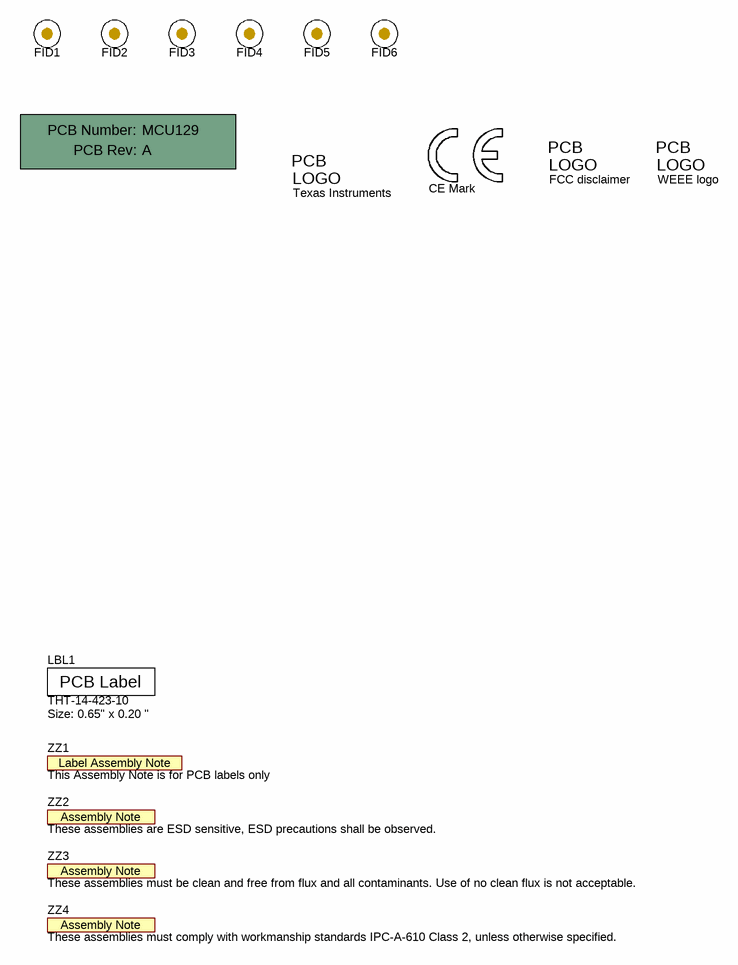
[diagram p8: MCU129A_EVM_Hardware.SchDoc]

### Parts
!PCB1  Printed Circuit Board  (value not drawn)  (mechanical)
FID1  Fiducial  [Fiducial10-20]  (value not drawn)
FID2  Fiducial  [Fiducial10-20]  (value not drawn)
FID3  Fiducial  [Fiducial10-20]  (value not drawn)
FID4  Fiducial  [Fiducial10-20]  (value not drawn)
FID5  Fiducial  [Fiducial10-20]  (value not drawn)
FID6  Fiducial  [Fiducial10-20]  (value not drawn)
LBL1  THT-14-423-10  Note: Size: 0.65" x 0.20 "  [Label_650x200]
Logo1  CE Mark  [CE_Mark_5mm]  (no BOM)
Logo2  Texas Instruments  [TI_Stacked_Overlay_Small]  (no BOM)
Logo3  FCC disclaimer  [FCC_disclaimer]  (no BOM)
Logo4  WEEE logo  [WEEE_Minimum]  (no BOM)
ZZ1  This Assembly Note is for PCB labels only  [AssemblyNoteLabel]  (no BOM)
ZZ2  These assemblies are ESD sensitive, ESD precautions shall be observed.  [AssemblyNote]  (no BOM)
ZZ3  These assemblies must be clean and free from flux and all contaminants. Use of no clean flux is not acceptable.  [AssemblyNote]  (no BOM)
ZZ4  These assemblies must comply with workmanship standards IPC-A-610 Class 2, unless otherwise specified.  [AssemblyNote]  (no BOM)

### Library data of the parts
!PCB1 = CMP-0003618-2: Manufacturer: Any; PartNumber: MCU129
FID1-FID6 = CMP-0077181-1: Fiducial mark.  There is nothing to buy or mount.
LBL1 = CMP-0003625-1: Thermal Transfer Printable Labels, 0.650" W x 0.200" H - 10,000 per roll; Manufacturer: Brady
Logo1 = CMP-0074844-2: Manufacturer: Texas Instruments; SymbolCreator: a0412235; AEC Category: Q200; CompType: IC
Logo2 = CMP-0074838-1: Texas Instrument Corporate Signature; SymbolCreator: a0412235; Lib Reference: TI_Logo; Library Reference: Logo
Logo3 = CMP-0074847-1: FCC_disclaimer
Logo4 = CMP-0074769-4: Manufacturer: Texas Instruments; AEC Category: Q200; CompType: IC
ZZ1 = CMP-0003616-3
ZZ2 = CMP-0077236-1
ZZ3 = CMP-0077237-1
ZZ4 = CMP-0077238-1

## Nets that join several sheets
+5V0: MCU129A_POWER_DAC_SECTION (18 pins), MCU129A_HIGH_DENSITY_CONN (J1.18 J1.20)
GND: MCU129A_POWER_DAC_SECTION (46 pins), MCU129A_MCU_ISO_EMULATION_CONN (53 pins), MCU129A_HIGH_DENSITY_CONN (26 pins)
VCC_3V3: MCU129A_POWER_DAC_SECTION (9 pins), MCU129A_MCU_ISO_EMULATION_CONN (56 pins)
3V3_OUT: MCU129A_POWER_DAC_SECTION (R53.2), MCU129A_HIGH_DENSITY_CONN (J1.28 U3.1)
3V3_OUT_INV: MCU129A_POWER_DAC_SECTION (U26.4), MCU129A_MCU_ISO_EMULATION_CONN (R30.2 R31.2 U12.10)
15W_PD: MCU129A_POWER_DAC_SECTION (R52.2 U25.4), MCU129A_HIGH_DENSITY_CONN (J1.26)
DAC_CLK: MCU129A_POWER_DAC_SECTION (U21.16), MCU129A_MCU_ISO_EMULATION_CONN (U12.13)
DAC_PICO: MCU129A_POWER_DAC_SECTION (U21.1), MCU129A_MCU_ISO_EMULATION_CONN (U12.12)
DAC_POCI: MCU129A_POWER_DAC_SECTION (U21.2), MCU129A_MCU_ISO_EMULATION_CONN (U12.11)
DAC_STE: MCU129A_POWER_DAC_SECTION (U21.15), MCU129A_MCU_ISO_EMULATION_CONN (R27.1 U12.14)
USB_D_N: MCU129A_POWER_DAC_SECTION (J5.A7 J5.B7 U24.2 U24.9), MCU129A_MCU_ISO_EMULATION_CONN (U9.93)
USB_D_P: MCU129A_POWER_DAC_SECTION (J5.A6 J5.B6 U24.1 U24.10), MCU129A_MCU_ISO_EMULATION_CONN (U9.94)
XDS_EEPROM_SCL: MCU129A_MCU_ISO_EMULATION_CONN (R11.1 U6.6 U9.112), MCU129A_HIGH_DENSITY_CONN (J1.23 U2.5 U2.6)
XDS_EEPROM_SDA: MCU129A_MCU_ISO_EMULATION_CONN (R12.1 U6.3 U9.111), MCU129A_HIGH_DENSITY_CONN (J1.25 U2.4 U2.7)
XDS_RXD: MCU129A_MCU_ISO_EMULATION_CONN (U8.6 U9.33), MCU129A_HIGH_DENSITY_CONN (R5.1)
XDS_TCK: MCU129A_MCU_ISO_EMULATION_CONN (U7.4 U9.35), MCU129A_HIGH_DENSITY_CONN (R3.2)
XDS_TDI: MCU129A_MCU_ISO_EMULATION_CONN (U7.5 U9.38), MCU129A_HIGH_DENSITY_CONN (R1.1)
XDS_TDO: MCU129A_MCU_ISO_EMULATION_CONN (U8.3 U9.37), MCU129A_HIGH_DENSITY_CONN (R2.1)
XDS_TMS: MCU129A_MCU_ISO_EMULATION_CONN (R24.1 U6.4 U7.6 U9.36), MCU129A_HIGH_DENSITY_CONN (R4.2)
XDS_TXD: MCU129A_MCU_ISO_EMULATION_CONN (U6.5 U9.34), MCU129A_HIGH_DENSITY_CONN (R6.1)

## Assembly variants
001: not fitted C1 C2 C3 C4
